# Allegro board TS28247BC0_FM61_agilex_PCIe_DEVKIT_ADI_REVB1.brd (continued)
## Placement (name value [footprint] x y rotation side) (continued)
R6090  0,DNI  [RESC1005X40L20L]  197.24 55.32 180 top
R6091  499E  [0402]  68.84 72.85 90 bottom
R6092  0  [0402]  68.89 59.01 90 bottom
R6093  0  [0402]  210.67 72.14 180 top
R6096  0  [0402]  211.18 60 0 bottom
R6097  DNI  [0402]  65.03 57.79 0 bottom
R6098  20.0K  [0402]  234.83 53.65 90 bottom
R6100  0  [RESC1005X40L20L]  199.07 55.34 180 top
R6101  0  [0402]  220.02 79.68 270 bottom
R6102  0  [0402]  228.07 55.88 45 bottom
R6103  0  [0402]  227.13 53.7 270 bottom
R6104  0  [0402]  231.58 54.33 0 bottom
R6105  0  [RESC1005X40L20L]  199.47 66.5 90 bottom
R6106  10.0K  [0402]  191.35 40.26 270 bottom
R6107  10.0K  [0402]  190.02 56.29 270 bottom
R6108  10.0K  [0402]  190.05 83.64 270 bottom
R6109  10.0K  [0402]  190.13 71.35 270 bottom
R6110  0  [RESC1005X40L20L]  190.1 72.98 90 bottom
R6111  0  [RESC1005X40L20L]  190.13 85.04 90 bottom
R6112  0  [RESC1005X40L20L]  190 57.74 90 bottom
R6113  0  [RESC1005X40L20L]  189.67 48.72 270 bottom
R6114  0  [RESC1005X40L20L]  196.1 63.93 180 bottom
R6115  0  [RESC1005X40L20L]  190.79 63.78 90 bottom
R6261  10.0K  [0402]  231.83 19.66 0 top
R6262  49.9K  [0402]  229.75 19.64 180 top
R6263  110K  [0402]  232.85 19.66 0 top
R6264  10k  [0402]  228.73 22.05 180 bottom
R6265  10.0K,DNI  [0402]  236.35 23.29 270 bottom
R6266  56.2K  [0402]  229.62 22.05 180 bottom
R6267  10.0K  [0402]  234.58 23.29 270 bottom
R6268  1.0  [0402]  235.49 24.31 90 top
R6269  10.0K,DNI  [0402]  233.84 19.64 0 top
R6270  0  [0402]  229.19 23.52 90 bottom
R6271  0  [0402]  231.78 22.48 90 bottom
R6272  10.0K,DNI  [0402]  234.78 19.64 180 top
R6273  0  [0402]  216.72 93.37 270 bottom
R6274  4.7K,DNI  [0402]  236.94 86.79 180 top
R6275  4.7K,DNI  [0402]  235.39 86.62 180 top
R6276  0.001 OHM  [RES_CSNL2512_0_005-0_006]  233.71 37.82 90 top
R6283  10.0K  [0402]  221.14 41.79 90 top
R6284  10.0K  [0402]  221.14 40.64 90 top
R6285  0  [0402]  222.03 40.64 90 bottom
R6286  0  [0402]  222.03 41.79 90 bottom
R6287  0,DNI  [0402]  221.13 37.01 90 top
R6288  0,DNI  [0402]  221.13 38.03 90 top
R6289  0  [0402]  220.58 39.27 0 top
R6290  0  [0402]  221.57 39.32 0 top
R6291  10  [0402]  230.77 37.06 270 top
R6292  10  [0402]  230.79 38.03 270 top
R6293  0  [0402]  227.74 23.02 180 bottom
R6294  0  [0402]  59.24 58.37 90 bottom
S1  PB Switch  [WURTH_6X3P5_TACT_SWITCH]  267.72 65.48 180 top
S2  PB Switch  [WURTH_6X3P5_TACT_SWITCH]  267.72 61.42 180 top
S3  PB Switch  [WURTH_6X3P5_TACT_SWITCH]  267.72 57.36 180 top
S4  PB Switch  [WURTH_6X3P5_TACT_SWITCH]  267.72 53.29 180 top
S5  PB Switch  [WURTH_6X3P5_TACT_SWITCH]  267.72 49.23 0 top
ST3  -  [SHORT]  208.62 58.88 225 bottom
ST11  -  [SHORT]  217.28 71.55 0 bottom
ST12  -  [SHORT]  68.89 60.3 0 bottom
ST13  -  [SHORT]  207.91 87.28 180 bottom
ST14  -  [SHORT]  212.48 46.18 90 bottom
ST15  -  [SHORT]  213.19 69.93 315 top
ST16  -  [SHORT]  69.02 74.09 0 bottom
ST17  -  [SHORT]  60.03 57.23 180 bottom
ST19  -  [SHORT]  231.6 47.78 180 bottom
ST20  -  [SHORT]  63.96 38.97 90 bottom
ST21  -  [SHORT]  216.01 78.56 0 top
ST31  -  [SHORT]  207.6 93.46 90 bottom
ST32  -  [SHORT]  233.76 17.94 90 top
SW1  TDA04H0SB1  [DIPSWITCH_SMT_QUAD]  213.5 31.82 180 bottom
SW2  DIPSWITCH4  [DIPSWITCH_SMT_QUAD]  8.52 71.76 90 bottom
SW3  DIPSWITCH4  [DIPSWITCH_SMT_QUAD]  8.52 64.39 90 bottom
SW4  TDA04H0SB1  [DIPSWITCH_SMT_QUAD]  8.52 46.99 90 bottom
SW5  SW_SLIDE_DPDT  [EG2207]  268.35 75.49 270 top
SW6  TDA04H0SB1  [DIPSWITCH_SMT_QUAD]  8.52 39.88 90 bottom
SW7  CVS-01TB  [DIPSWITCH_SMT_SINGLE]  265.31 42.75 0 top
TP1  TP, 0.016", Thru Hole  [30MIL_TP]  238.67 61.19 0 top
TP2  TP, 0.016", Thru Hole  [30MIL_TP]  237.37 61.22 0 top
TP16  TESTPOINT  [30MIL_TP]  214.42 27.26 0 top
TP17  TESTPOINT  [30MIL_TP]  214.42 24.72 0 top
TP19  TEST PAD  [PADSTYLE1]  211.08 99.77 0 top
TP20  TESTPOINT  [30MIL_TP]  219.37 27.26 0 top
TP28  TESTPOINT  [30MIL_TP]  203.72 53.83 0 top
TP29  TESTPOINT  [30MIL_TP]  232.39 45.16 0 top
TP30  TP, 0.016", Thru Hole  [30MIL_TP]  206.97 63.78 0 top
TP31  TP, 0.016", Thru Hole  [30MIL_TP]  205.7 63.83 0 top
TP32  TESTPOINT  [30MIL_TP]  68.1 64.67 0 top
TP33  TESTPOINT  [30MIL_TP]  65.79 79.33 0 top
TP34  TESTPOINT  [30MIL_TP]  61.73 49.58 0 top
TP35  TESTPOINT  [30MIL_TP]  61.5 63.55 0 top
TP38  TP, 0.016", Thru Hole  [30MIL_TP]  213.65 72.95 0 top
TP39  TP, 0.016", Thru Hole  [30MIL_TP]  215.15 73.23 0 top
TP41  TESTPOINT  [30MIL_TP]  215.68 63.78 0 top
TP42  TESTPOINT  [30MIL_TP]  204.68 63.66 180 bottom
TP45  TESTPOINT  [30MIL_TP]  232.37 81.69 0 top
TP46  TESTPOINT  [30MIL_TP]  230.79 61.8 0 top
TP47  TP, 0.016", Thru Hole  [30MIL_TP]  234.45 45.04 0 top
TP971  TESTPOINT  [30MIL_TP]  228.48 35.26 0 top
TP1005  -  [30MIL_TP]  236.33 22.41 0 top
U1  MAX3378E  [TSSOP-14]  103.89 98.38 90 bottom
U2  AGFB014R24_2486A  [FBGA2486A_HEX]  116.21 61.93 0 top
U3  MAX3378E  [TSSOP-14]  94.62 98.38 90 bottom
U4  MAX3378E  [TSSOP-14]  154.44 25.61 270 bottom
U5  MAX3378E  [TSSOP-14]  82.94 25.61 270 bottom
U6  MT25QU02GCBB3E12-1SIT  [T-PBGA24]  206.51 29.49 270 top
U7  KSZ9031RN  [QFN48]  28.17 86.7 270 bottom
U8  EY1501DI-ADJ  [DFN-10]  53.35 94.82 90 bottom
U9  SN74AUP1G126DCK  [SC70_TI]  25.92 67.01 90 bottom
U10  SN74AUP1T17DCKR  [SC70_TI]  16.14 73.36 0 bottom
U11  FT232R  [QFN32-FTDI]  20.71 70.82 0 bottom
U12  SN74AUP1T17DCKR  [SC70_TI]  28.96 71.96 270 bottom
U13  TPD4S012DRYR  [SON6]  17.99 104.57 180 top
U14  LSF0108PWR  [TSSOP20]  44.97 95.96 180 bottom
U15  -  [TPS22902BYFPR]  43.57 107.52 0 bottom
U16  MTFC8GAKAJCN-4M IT  [VFBGA-153]  29.47 100.15 270 bottom
U17  Si5341A-D10654-GM  [QFN64_9X9_SI5341]  48.78 25.99 0 top
U18  Si52202-A01AGM  [SI52202]  210.83 103.71 90 top
U19  510MCA50M0000AAGR  [SI510]  38.87 41.86 270 bottom
U20  FXMA2102UMX  [UMLP]  29.09 48.59 270 bottom
U21  FXMA2102UMX  [UMLP]  17.15 48.59 270 bottom
U22  FXMA2102UMX  [UMLP]  23.12 48.59 270 bottom
U23  MAX3378E  [TSSOP-14]  88.15 98.38 90 bottom
U24  MAX811  [SOT-143]  266.96 63.71 90 bottom
U25  MAX811  [SOT-143]  21.98 27.51 90 top
U26  10M04SCU169  [BGA169-0R80-11X11]  31.63 23.62 270 top
U27  TPD2EUSB30  [DRT]  5.98 26.09 90 top
U28  CY7C68013A_QFN  [QFN56]  14.36 26.57 90 top
U29  TS3A5018RSVR  [UQFN-16]  33.15 42.5 270 bottom
U30  10M16SA U169_1  [BGA169-0R80-11X11]  254.15 27.46 270 top
U32  MAX6581  [24TQFN-EP]  73.79 85.68 90 top
U33  FDMC2514SDC  [FDMC8878_VER2]  251.47 93.47 90 top
U34  FDMC2514SDC  [FDMC8878_VER2]  246.26 93.47 270 top
U35  LTC4357  [DFN6_EPAD]  256.8 101.02 0 top
U36  LTC4365-1  [DFN8-EPAD_3X2]  245.98 102.24 0 bottom
U37  LTC4359  [MSOP-8]  244.86 87.25 180 top
U38  FDMC2514SDC  [FDMC8878_VER2]  257.06 79.07 0 top
U39  FDMC2514SDC  [FDMC8878_VER2]  252.1 80.6 0 top
U40  LTC4357  [DFN6_EPAD]  261.75 79.81 270 bottom
U41  LTC4365-1  [DFN8-EPAD_3X2]  247.86 79.99 0 bottom
U42  TPS3700  [DDC]  257.69 55.45 90 top
U43  LTM4625  [LGA25]  244.61 53.29 90 top
U44  EY1501di-adj  [DFN-11]  253.25 42.5 90 top
U45  EY1501di-adj  [DFN-11]  25.49 41.08 180 bottom
U46  LTC7151SEV  [LQFN_28_5MMX4MM]  231.88 25.17 180 top
U47  LTC3888IUHG-1#PBF  [QFN40P500X800X80-53N]  199.14 61.04 0 top
U50  EY1501di-adj  [DFN-11]  210.02 51.16 270 top
U51  LTM4623EY#PBF  [BGA25C127P5X5_625X625X262]  209.28 58.22 90 top
U52  REF1112AIDBZR  [SOT23-3]  206 27.64 90 bottom
U55  LTM4678EY#PBF  [BGA144C127P12X12_1600X1600X626]  225.36 71.87 180 top
U56  LTM4608AEV#PBF  [LGA68S127P7X11_900X1500X292]  69.43 57.1 90 top
U57  LTM4643EY#PBF  [BGA77C127P7X11_900X1500X262N]  207.14 83.9 90 top
U58  LTM4643EY#PBF  [BGA77C127P7X11_900X1500X262N]  205.49 41.23 90 top
U59  TPS51200  [VSON-11]  51.57 103.96 270 bottom
U60  TPS51200  [VSON-11]  207.58 20.44 90 bottom
U61  LTM4623EY#PBF  [BGA25C127P5X5_625X625X262]  212.58 69.32 90 bottom
U62  FDMC2514  [FDMC8878_VER2]  37.73 70.82 180 bottom
U63  LTC4365-1  [DFN8-EPAD_3X2]  32.77 71.07 0 bottom
U64  EY1501di-adj  [DFN-11]  17.23 41.08 180 bottom
U65  LTM4608AEV#PBF  [LGA68S127P7X11_900X1500X292]  69.45 70.92 90 top
U66  LTM4668IY#PBF  [BGA49C80P7X7_625X625X230N]  54.53 55.87 180 bottom
U67  MAX3378E  [TSSOP-14]  73.67 98.38 90 bottom
U68  MAX3378E  [TSSOP-14]  81.29 98.38 90 bottom
U70  LTM4668IY#PBF  [BGA49C80P7X7_625X625X230N]  69.07 39.14 0 top
U71  LTM4686EV-1#PBF  [LGA108C127P9X12_1190X1600X192N]  230.26 53.04 90 top
U72  9DML0441AKILF  [24-VFQFPN]  203.84 102.06 90 bottom
U73  24AA64-I  [MSOP8]  244.99 64.21 270 top
U76  LTC7051AV#PBF  [ANALOG_LQFN-42P]  186.1 83.39 0 top
U77  LTC7051AV#PBF  [ANALOG_LQFN-42P]  186.1 70.74 0 top
U78  LTC7051AV#PBF  [ANALOG_LQFN-42P]  186.1 55.2 0 top
U79  LTC7051AV#PBF  [ANALOG_LQFN-42P]  186.1 39.02 0 top
U124  LTM4622EV#PBF  [LGA25C127P5X5_625X625X192N]  199.52 51.51 90 bottom
U125  LTM4657EY  [LTC-BGA-49-1518]  210.32 95.46 90 top
U126  INA219AIDCN  [SOT23-8P]  226.35 38.53 180 top
V1  VIA_1  [STAR_VIA]  22.74 89.74 90 bottom
Y1  25MHz  [OSC7050]  36.71 87.71 180 bottom
Y2  48MHz  [XTAL_3MMX2MM]  41.3 26.24 90 top
Y3  25.00MHz  [XTAL_FA-128]  215.53 103.2 270 top
Y4  24.00MHz  [XTAL_FA-128]  12.61 18.82 180 top

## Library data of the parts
B1 B2 = Molex_QSFPDD_Cage
C1-C3 C5 C7 C9 C11 C13 C15 C17-C19 C24-C26 C31 C34 C37-C39 C41 C45 C47 C49 C51 C53-C55 C58 C60 C63 C69 C73-C75 C77 C79 C81 C83 C85 C87 C89-C91 C96 C97 C100 C103 C106 C110 C112 C114 C116 C118 C120 C122-C124 C130 C136 C139 C142 C144 C148 C152 C157 C159 C163 C167 C173 C174 C176 C215 C237-C239 C262 C263 C266 C284-C287 C294-C324 C335-C338 C340-C344 C347-C354 C357-C367 C369-C379 C381-C391 C393 C396 C398-C404 C407-C418 C420 C426 C432 C434 C442-C444 C448 C454 C458 C459 C466 C467 C557 C561 C652 C658 C660 C661 C672 C673 C683 C687 C702-C705 C707 C708 C762-C801 C828-C834 C1232-C1235 C1244-C1246 C1249 C1250 C1292-C1297 C1427 C1440 C1441 C1446 C1447 C1450 C1472-C1502 C1518-C1524 C1654 C1655 C1816 C1822 C1823 C1840 C1868 C1873 C1874 C1895 C1900-C1902 C1904 C1914 C1933-C1935 C1940 C1956 C1957 C1966 C1967 C1975 C1976 C1978 C1979 C1990 C1994 C1996 C1998 C2002-C2004 C2007-C2010 C2012 C2017-C2020 C2025-C2028 C2031-C2033 C2038 C7777 C7778 = CAP: User Part Number: PART#; Tolerance: TOL
C4 C6 C8 C10 C12 C14 C27-C29 C35 C40 C44 C46 C48 C50 C57 C64 C70 C71 C76 C78 C80 C82 C84 C86 C98 C99 C101 C107 C109 C111 C113 C115 C117 C119 C131 C134 C140 = Cap 10000PF 50V 0402: User Part Number: PART#; Tolerance: TOL
C16 C20 C21 C32 C52 C61 C65 C66 C88 C92 C93 C104 C121 C125 C126 C137 C156 C171 C339 C427 C706 C802-C807 C1410 C1445 C1660 C1663 C1674 C1887-C1889 C1891-C1894 C1896-C1898 C1907 C1913 C1915-C1917 C1919-C1924 C1926 C1930-C1932 C1941 C1947 C1952-C1954 C1962-C1964 = CAP: Tolerance: *; User Part Number: *
C22 C23 C33 C62 C67 C68 C94 C95 C105 C127 C138 = CAP 10uF +/-10% 25V 1210: User Part Number: *; Tolerance: *
C42 = Cap 10000PF 50V 0402: User Part Number: PART#; Tolerance: TOL; signal model: CAP_0402_0.22UF_0.22uF
C43 C172 C175 C177-C214 C217 C218 C220-C222 C224-C228 C231 C232 C235 C240-C244 C247-C249 C251 C254-C256 C258-C260 C268 C269 C271-C274 C355 = CAP: User Part Number: PART#; Tolerance: TOL; signal model: CAP_0402_0.22UF_0.22uF
C128 = CAP 10uF +/-10% 25V 1210: User Part Number: *; Tolerance: *; signal model: CAP_0402_0.1UF_0.1uF
C129 C133 C325-C334 C345 = CAP: User Part Number: PART#; Tolerance: TOL; signal model: CAP_0402_0.1UF_0.1uF
C132 = Cap 10000PF 50V 0402: User Part Number: PART#; Tolerance: TOL; signal model: CAP_0402_0.1UF_0.1uF
C143 C145-C147 C149-C151 C153-C155 C158 C160-C162 C164-C166 C168-C170 C234 C236 C264 C265 C267 C356 C368 C380 C394 C397 C405 C406 C456 C457 C460-C465 C558-C560 C653-C657 C659 C662-C666 C668-C671 C682 C684-C686 C840-C842 C858-C861 C1202 C1208-C1210 C1212 C1236 C1241 C1247 C1248 C1286-C1291 C1321 C1341-C1344 C1361-C1364 C1384-C1387 C1405-C1408 C1423 C1430-C1433 C1503-C1517 C1819-C1821 C1910 C1911 C1944 C1945 C7775 C7776 = CAP: User Part Number: *; Tolerance: *
C216 C219 C223 C229 C230 C233 C250 C252 C253 C257 C261 C270 C555 C667 = CAP: User Part Number: *; Tolerance: *; signal model: CAP_0402_0.22UF_0.22uF
C245 C246 = Cap 39PF 5% 50V 0402: User Part Number: PART#; Tolerance: TOL; signal model: CAP_0402_0.22UF_0.22uF
C275 C276 = CAP: signal model: CAP_0402_0.22UF_0.22uF
C277-C283 C289-C293 C737 C836-C839 C843-C857 C1201 C1203-C1207 C1211 C1216-C1220 C1223-C1225 C1228-C1231 C1237-C1240 C1251-C1285 C1304-C1314 C1317-C1320 C1325-C1340 C1345-C1360 C1365 C1366 C1368-C1383 C1389-C1404 C1421 C1422 C1434-C1439 C1448 C1449 = CAP
C346 = CAP: User Part Number: *; Tolerance: *; signal model: CAP_0402_0.1UF_0.1uF
C395 C453 C455 C709-C711 C1665 C1818 C1839 C1909 C1943 C1995 C1997 C1999 C2034 C2036 C2039 = Cap, NP, 0402: User Part Number: PART#; Tolerance: TOL
C419 C422-C424 C445-C447 C449-C452 C1426 C1667 C1669 C1670 C1867 C1872 C1903 C1908 C1912 C1925 C1942 C1946 C1948 C1949 C1958 C1959 C1977 C1986 C1991 C2000 C2001 C2029 C2030 C2035 C2037 = Cap, NP, 1206: Tolerance: *; User Part Number: *
C421 C425 C428-C431 C433 C435-C441 C679 C1196 C1197 C1199 C1200 C1213 C1222 C1227 C1242 C1243 C1298 C1299 C1302 C1303 C1315 C1323 C1324 C1367 C1388 C1424 C1425 C1428 C1429 C1443 C1886 C1899 C1918 C1928 C1929 C7771 C7772 = PCAP
C680 = PCAP: User Part Number: *; Tolerance: *
C681 = CAP_NP: User Part Number: PART#; Tolerance: TOL
C808-C812 C814 C815 C817-C819 C821 C825 C835 C1214 C1215 = PCAP: Tolerance: TOL; User Part Number: PART#
C1525 = CAP: User Part Number: PART#; Tolerance: TOL; signal model: CAP_0402_DNI_DNI
C1550 C1656 C1673 C1817 C1833 C1834 C1848 C1849 C1859 C1860 C1875 C1876 C1950 C1960 C1987 = Cap, NP, 0402: Tolerance: TOL; User Part Number: PART#
C1659 C1951 C1961 = CAP: Tolerance: *; User Part Number: 150-3503
C1824-C1827 = T545X337K016ATE025
C1829 C1831 C1832 C1835-C1838 C1850-C1853 C1861-C1864 C1877-C1880 C1905 C1906 C1980 C1981 C1988 C1989 C1992 C1993 C2011 C7768 C7770 = Cap, NP, 1206: User Part Number: *; Tolerance: *
C1841 C1844-C1847 C1856 C1869 C1883 = CAPPOL
C1842 C1843 C1857 C1858 C1870 C1871 C1884 C1885 C2013-C2016 C2021-C2024 = Cap, NP, 0805: Tolerance: TOL; User Part Number: PART#
C1890 C7779 = TCN4227M025R0100
C7761 C7762 C7764-C7766 C7773 C7774 = CAP: Tolerance: TOL; User Part Number: PART#
C7763 = CAP NP: User Part Number: *; Tolerance: *
C7767 C7769 = Cap, NP, 1206: Tolerance: TOL; User Part Number: GRM21BR61E106K
D2 D3 D7 D9-D14 D21 D23 = LED_WURTH: User Part Number: *; Tolerance: *
D4-D6 = ESD_DIODE_DUAL
D8 = LED_0: User Part Number: *; Tolerance: *
D15 D16 = TVS_5p0SMDJ12A
D22 D24 = APHB1608CGKSYKC
D25 = PMEG2005AEL,315
FB9-FB16 FB19-FB24 FB30 FB31 FB33 FB36-FB38 FB40-FB42 FB45 L1 L2 L8 = BEAD_FERRITE_SM: User Part Number: PART#; Tolerance: TOL
FB17 FB18 FB25-FB28 = BEAD_FERRITE_SM: User Part Number: *; Tolerance: *
FB29 = INDUCTOR: User Part Number: PART#; Tolerance: TOL
HW1 = LIGHTPIPE_P-U90-1101-T00A-BP_2
J1-J4 = DDR4x72x288_1
J5 J6 = 2027180100
J7 = PCIE_Bracket_X16_1
J8 = ENET_L829-1J1T-43_2
J9 = CON2
J10 J13 = MICRO_USB_CONN
J11 = SD_SKT_1: User Part Number: *
J12 = 2-767004-2
J14 = 0702461004
J15 = FAN_Conn_0
J16 = 2X4_PCIE_ATX_1: User Part Number: PART#; Tolerance: TOL
J17 = 1x3_HDR_TH
J22 = 95278-101A04LF
L3-L7 = IND Ferrite 0603 3A/30 Ohms: User Part Number: *; Tolerance: *
L9 = IND Ferrite 0402 300mA/220: User Part Number: PART#; Tolerance: TOL
L14-L20 = INDUCTOR IRON
L23-L26 = FP1008R6-R150-R
L30 = XGL5030-351MEC
MTH1-MTH6 = MNT HOLE_1
Q1-Q4 = NMOS_3Pin: Tolerance: *; User Part Number: *
Q5-Q11 Q24-Q29 = PWRMOSFET_EN_GSD_0: Tolerance: *; User Part Number: *
Q12 = PSMN1R0-30YLD_0
Q13 = PWRMOSFET_EN_GSD_1: Tolerance: *; User Part Number: *
R1 R2 R17 R18 R54 R55 R68 R69 = RESISTOR: Tolerance: *; User Part Number: *
R3-R6 R15 R16 R21-R23 R31-R50 R53 R56 R57 R59 R66 R67 R70-R73 R80-R99 R104-R106 R108-R112 R114 R116 R120-R126 R134-R140 R143-R145 R154 R155 R157-R163 R165-R167 R171-R180 R187 R188 R190 R196 R201-R204 R206 R208-R214 R216 R236 R241-R245 R247 R260 R261 R263 R265-R305 R307 R308 R310 R312 R313 R315 R318-R320 R322-R326 R328-R332 R334-R340 R344-R346 R348-R351 R354 R356 R357 R361 R363-R365 R367 R368 R370 R371 R373 R374 R377-R380 R382 R385 R387 R390 R395-R402 R405-R407 R409-R412 R414-R419 R421 R423-R431 R433-R449 R546-R549 R647-R658 R668 R669 R671-R677 R680-R682 R703-R711 R714-R724 R729-R735 R773-R788 R793 R794 R801-R823 R828-R830 R832 R833 R978 R5757 R5758 R5772-R5774 R5780 R5788 R5789 R5928 R5930 R5932 R5934 R5939-R5942 R5957 R5960 R5963-R5978 R5981-R5983 R5985 R5988-R5992 R5994 R5995 R5997-R6001 R6004 R6006 R6011 R6012 R6015-R6024 R6026-R6037 R6039-R6043 R6045 R6056 R6059-R6062 R6075-R6077 R6083-R6086 R6091-R6093 R6096-R6098 R6101-R6104 R6106-R6109 R6273-R6275 R6283-R6294 = RESISTOR: User Part Number: PART#; Tolerance: TOL
R7-R9 R24 R25 R58 R60 R74 R246 R248-R259 R262 R264 R408 R420 R470 R471 R514-R516 R678 R679 = RES 0 OHM 5% 1/16W 0402 SMD: User Part Number: PART#; Tolerance: TOL; signal model: RES_0_OHM_5%_1/16W_0402_SMD_0402_0_0
R10 R26 R61 R75 R107 R117 R118 R789-R792 = RESISTOR: User Part Number: PART#; Tolerance: TOL; signal model: RESISTOR_0402_10.0K_10.0K
R11-R13 R27-R29 R62-R64 R76-R78 R142 R147 R149 R150 R153 R358 R831 = RESISTOR: User Part Number: PART#; Tolerance: TOL; signal model: RESISTOR_0402_DNI_DNI
R14 R19 R20 R30 R65 R79 R189 R191-R195 R205 R207 = RESISTOR: User Part Number: *; Tolerance: *
R100 R101 R238 R239 R321 R327 R670 R797-R800 R824-R827 R834 R5980 R6002 R6003 R6005 R6007 R6014 = RES 0 OHM 5% 1/16W 0402 SMD: User Part Number: PART#; Tolerance: TOL
R102 R103 R141 R146 R148 R151 R152 R156 = RESISTOR: User Part Number: PART#; Tolerance: TOL; signal model: RESISTOR_0402_4.7K_4.7K
R113 = RESISTOR_0402: User Part Number: PART#; Tolerance: TOL; signal model: RESISTOR_0402_0402_33_33
R115 R119 R341-R343 R347 R352 R353 R355 R359 = RESISTOR: User Part Number: PART#; Tolerance: TOL; signal model: RESISTOR_0402_1K_1K
R127 R129-R133 R169 R218-R226 = RESISTOR: User Part Number: PART#; Tolerance: TOL; signal model: RESISTOR_0402_0402_33_33
R128 R197-R200 R391-R394 = RESISTOR: User Part Number: PART#; Tolerance: TOL; signal model: RESISTOR_0402_0_0
R164 R333 = R: User Part Number: PART#; Tolerance: TOL
R181-R186 R215 R217 = RESISTOR: User Part Number: PART#; Tolerance: TOL; signal model: RESISTOR_0402_1.00K_1.00K
R227-R235 = RESISTOR: User Part Number: PART#; Tolerance: TOL; signal model: RESISTOR_0402_10K_10K
R306 R309 R311 R314 R316 R317 = RESISTOR_0: User Part Number: PART#; Tolerance: TOL
R360 R362 R369 R372 R375 R376 R381 R383 R384 R386 = RES 10 OHM 1.0% 1/16W 0402: User Part Number: PART#; Tolerance: TOL
R404 R413 R422 R432 R5993 R5996 R6063 R6067 R6074 = RES: User Part Number: PART#; Tolerance: TOL
R667 = RESISTOR_0603: Tolerance: *; User Part Number: *
R873-R877 R6264 = Resistor, 0402: Tolerance: TOL; User Part Number: PART#
R5776 R5777 R5785 R5787 R5929 R5931 R5933 R5935-R5938 R5958 R5984 R5986 R5987 R6013 R6038 R6044 R6055 R6057 R6058 R6065 R6066 R6071-R6073 R6078 R6079 = Resistor, 0402: User Part Number: PART#; Tolerance: TOL
R5784 R5786 = RESISTOR_0402: User Part Number: PART#; Tolerance: TOL
R5943-R5947 R5949 R5951 R5952 R5954 R5955 R5961 R5962 R6087-R6090 R6100 R6105 R6110-R6115 = Resistor, 0402_0: Tolerance: TOL; User Part Number: PART#
R5948 = Resistor, 0603_0: Tolerance: *; User Part Number: *
R5956 = res: User Part Number: PART#; Tolerance: TOL; alternate symbols: ((T:0402_BGA;B:0402_BGA))
R6008 R6276 = CSNL2512FT5L00
R6261-R6263 R6265-R6272 = RESISTOR: Tolerance: TOL; User Part Number: PART#
S1-S5 = TS-A02SA-2-S100_0: User Part Number: *
ST3 ST11-ST17 ST19-ST21 ST31 ST32 = SHORT: User Part Number: *
SW1-SW4 SW6 = SPST4
SW5 = SW_SLIDE_DPDT: User Part Number: PART#; Tolerance: TOL
SW7 = SPST4_0
TP1 TP2 TP16 TP17 TP20 TP28 TP30 TP31 TP38 TP39 TP47 TP971 TP1005 = TP, 0.016", Thru Hole
TP19 = PAD_STYLE_C
TP29 TP32-TP35 TP41 TP42 TP45 TP46 = TESTPOINT
U1 U3-U5 U23 U67 U68 = MAX3378E_0: User Part Number: PN; Tolerance: TOL
U2 = FM6_2486A_V1.5
U6 = MT25QU01GBBB: User Part Number: *; Tolerance: *
U7 = KSZ9031RN_4
U8 = EY1501DI-ADJ
U9 = SN74AUP1G126DCK
U10 U12 = SN74AUP1G17DCK
U11 = FT232R_2: User Part Number: *
U13 = TPD4S012DRYR
U14 = LSF0108PWR
U15 = TPS22902BYFPR
U16 = MTFC8GAKAJCN-4M IT
U17 = Si5341A-A-GM_1
U18 = Si52202-A01AGM
U19 = Si510-DualCMOS
U20-U22 = FXMA2102UMX
U24 U25 = MAX811: Tolerance: TOL; User Part Number: PART#
U26 = 10M04SCU169
U27 = TPD2EUSB30: Tolerance: *; User Part Number: *
U28 = CY7C68013A_56QFN: User Part Number: *
U29 = TS3A5018RSVR_0
U30 = 10M16SA U169_1
U32 = MAX6581_0
U33 U34 U38 U39 U62 = FDMC8878_VER2: User Part Number: *
U35 U40 = LTC4357: User Part Number: *
U36 U41 U63 = LTC4365_DFN: User Part Number: *
U37 = LTC4359
U42 = TPS3700: User Part Number: pn
U43 = LTC4625EY
U44 U45 U50 U64 = EY1501di-adj
U46 = LTC3543EDCB_0
U47 = LTC3888IUHG-1#PBF
U51 U61 = LTM4623EY#PBF
U52 = REF1112
U55 = LTM4678EY#PBF
U56 U65 = LTM4608AEV#PBF_V1
U57 U58 = LTM4643EY#PBF
U59 U60 = TPS51200: User Part Number: *
U66 U70 = LTM4668IY#PBF
U71 = LTM4686EV-1#PBF
U72 = 9DML0451AKILF
U73 = 24AA64-I
U76-U79 = LTC7051AV#PBF
U124 = LTM4622EV#PBF
U125 = LTM4657-BGA_0
U126 = INA219AIDCN
V1 = VIA_1
Y1 = OSC_ALT
Y2 = CRYSTAL_SM_13
Y3 Y4 = CRYSTAL_SM_13: User Part Number: *

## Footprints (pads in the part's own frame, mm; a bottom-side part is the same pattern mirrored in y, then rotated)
1X3_HDR_TH
  rect 1.524x1.524 hole 1.016: 1(0,0)
  round 1.524 hole 1.016: 2(2.54,0) 3(5.08,0)
8MM_CAN
  rect 2.032x4.013 smd: 1(0,3.257) 2(0,-3.257)
24-VFQFPN
  oval 0.787x0.279 smd: 1(-1.994,1.25) 2(-1.994,0.75) 3(-1.994,0.25) 4(-1.994,-0.25) 5(-1.994,-0.75) 6(-1.994,-1.25) 13(1.994,-1.25) 14(1.994,-0.75) 15(1.994,-0.25) 16(1.994,0.25) 17(1.994,0.75) 18(1.994,1.25)
  oval 0.279x0.787 smd: 7(-1.25,-1.994) 8(-0.75,-1.994) 9(-0.25,-1.994) 10(0.25,-1.994) 11(0.75,-1.994) 12(1.25,-1.994) 19(1.25,1.994) 20(0.75,1.994) 21(0.25,1.994) 22(-0.25,1.994) 23(-0.75,1.994) 24(-1.25,1.994)
  rect 2.413x2.413 smd: 25(0,0)
24TQFN-EP
  oval 0.787x0.279 smd: 1(-1.994,1.25) 2(-1.994,0.75) 3(-1.994,0.25) 4(-1.994,-0.25) 5(-1.994,-0.75) 6(-1.994,-1.25) 13(1.994,-1.25) 14(1.994,-0.75) 15(1.994,-0.25) 16(1.994,0.25) 17(1.994,0.75) 18(1.994,1.25)
  oval 0.279x0.787 smd: 7(-1.25,-1.994) 8(-0.75,-1.994) 9(-0.25,-1.994) 10(0.25,-1.994) 11(0.75,-1.994) 12(1.25,-1.994) 19(1.25,1.994) 20(0.75,1.994) 21(0.25,1.994) 22(-0.25,1.994) 23(-0.75,1.994) 24(-1.25,1.994)
  rect 2.413x2.413 smd: 25(0,0)
30MIL_TP
  round 0.762 smd: 1(0,0)
0201
  rect 0.45x0.4 smd: 1(-0.35,0) 2(0.35,0)
0402
  rect 0.508x0.508 smd: 1(0,0.445) 2(0,-0.445)
0603
  rect 1.016x1.016 smd: 1(-0.762,0) 2(0.762,0)
0805
  rect 1.6x1.321 smd: 1(0,0.95) 2(0,-0.95)
1206
  rect 1.27x1.778 smd: 1(-1.524,0) 2(1.524,0)
1210
  rect 1.27x2.794 smd: 1(-1.524,0) 2(1.524,0)
1411
  rect 1.524x2.464 smd: 1(-1.612,0) 2(1.612,0)
2917
  rect 2.54x2.743 smd: 1(-3.175,0) 2(3.175,0)
7343P
  rect 2.54x2.743 smd: 1(-3.175,0) 2(3.175,0)
2027180100
  oval 1.6x0.356 smd: 1(2.4,7) 2(2.4,6.2) 3(2.4,5.4) 4(2.4,4.6) 5(2.4,3.8) 6(2.4,3) 7(2.4,2.2) 8(2.4,1.4) 9(2.4,0.6) 10(2.4,-0.2) 11(2.4,-1) 12(2.4,-1.8) 13(2.4,-2.6) 14(2.4,-3.4) 15(2.4,-4.2) 16(2.4,-5) 17(2.4,-5.8) 18(2.4,-6.6) 19(2.4,-7.4) 20(11.19,-7) 21(11.19,-6.2) 22(11.19,-5.4) 23(11.19,-4.6) 24(11.19,-3.8) 25(11.19,-3) 26(11.19,-2.2) 27(11.19,-1.4) 28(11.19,-0.6) 29(11.19,0.2) 30(11.19,1) 31(11.19,1.8) 32(11.19,2.6) 33(11.19,3.4) 34(11.19,4.2) 35(11.19,5) 36(11.19,5.8) 37(11.19,6.6) 38(11.19,7.4) 39(5.33,7) 40(5.33,6.2) 41(5.33,5.4) 42(5.33,4.6) 43(5.33,3.8) 44(5.33,3) 45(5.33,2.2) 46(5.33,1.4) 47(5.33,0.6) 48(5.33,-0.2) 49(5.33,-1) 50(5.33,-1.8) 51(5.33,-2.6) 52(5.33,-3.4) 53(5.33,-4.2) 54(5.33,-5) 55(5.33,-5.8) 56(5.33,-6.6) 57(5.33,-7.4) 58(8.26,-7) 59(8.26,-6.2) 60(8.26,-5.4) 61(8.26,-4.6) 62(8.26,-3.8) 63(8.26,-3) 64(8.26,-2.2) 65(8.26,-1.4) 66(8.26,-0.6) 67(8.26,0.2) 68(8.26,1) 69(8.26,1.8) 70(8.26,2.6) 71(8.26,3.4) 72(8.26,4.2) 73(8.26,5) 74(8.26,5.8) 75(8.26,6.6) 76(8.26,7.4)
  round 3.023 hole 1.549: 77(-9.1,8.4) 78(-9.1,-8.4)
AMPHENOL_95278-X01X04LF
  rect 1.27x2.54 smd: 1(-1.27,-2.73) 2(-1.27,2.73) 3(1.27,-2.73) 4(1.27,2.73)
ANALOG_LQFN-42P
  rect 0.7x0.25 smd: 1(-2.4,3.5) 2(-2.4,3) 3(-2.4,2.5) 4(-2.4,2) 5(-2.4,1.5) 6(-2.4,1) 7(-2.4,0.5) 9(-2.4,-0.5) 10(-2.4,-1) 11(-2.4,-1.5) 12(-2.4,-2) 13(-2.4,-2.5) 14(-2.4,-3) 15(-2.4,-3.5) 22(2.4,-3.5) 23(2.4,-3) 24(2.4,-2.5) 25(2.4,-2) 26(2.4,-1.5) 27(2.4,-1) 28(2.4,-0.5) 29(2.4,0) 30(2.4,0.5) 31(2.4,1) 32(2.4,1.5) 33(2.4,2) 34(2.4,2.5) 35(2.4,3) 36(2.4,3.5)
  custom 0.312x0.312 smd: 8(-2.4,0)
  custom 0.238x0.238 smd: 16(-2,-3.9) 42(-2,3.9)
  rect 0.25x0.7 smd: 17(-1,-3.9) 19(0,-3.9) 20(1,-3.9) 38(1,3.9) 39(0,3.9) 41(-1,3.9)
  custom 0.35x0.35 smd: 18(-0.5,-3.9) 40(-0.5,3.9)
  custom 0.288x0.288 smd: 21(1.5,-3.9) 37(1.5,3.9)
  rect 0.7x1.5 smd: 43(0.85,0)
B2
  rect 1.778x2.54 smd: 1(-1.524,0) 2(1.524,0)
BEL_L829-1J1T-43
  round 3.251 hole 3.251 unplated: (-9.906,-6.604) (-0.254,-6.604)
  rect 1.397x1.397 hole 0.889: 1(0,0)
  round 1.397 hole 0.889: 2(-2.032,0) 3(-4.064,0) 4(-6.096,0) 5(-8.128,0) 6(-10.16,0) 7(1.016,2.54) 8(-1.016,2.54) 9(-3.048,2.54) 10(-7.112,2.54) 11(-9.144,2.54) 12(-11.176,2.54)
  round 1.778 hole 1.27: 13(2.438,-12.954) 14(2.438,-15.494) 15(-12.598,-10.414) 16(-12.598,-12.954) 17(-12.598,-15.494)
  round 2.337 hole 1.575: 18(3.708,-6.604) 19(-13.868,-6.604)
BGA25C127P5X5_625X625X262
  round 0.63 smd: A1(-2.54,2.54) A2(-1.27,2.54) A3(0,2.54) A4(1.27,2.54) A5(2.54,2.54) B1(-2.54,1.27) B2(-1.27,1.27) B3(0,1.27) B4(1.27,1.27) B5(2.54,1.27) C1(-2.54,0) C2(-1.27,0) C3(0,0) C4(1.27,0) C5(2.54,0) D1(-2.54,-1.27) D2(-1.27,-1.27) D3(0,-1.27) D4(1.27,-1.27) D5(2.54,-1.27) E1(-2.54,-2.54) E2(-1.27,-2.54) E3(0,-2.54) E4(1.27,-2.54) E5(2.54,-2.54)
BGA49C80P7X7_625X625X230N
  round 0.45 smd: A1(-2.4,2.4) A2(-1.6,2.4) A3(-0.8,2.4) A4(0,2.4) A5(0.8,2.4) A6(1.6,2.4) A7(2.4,2.4) B1(-2.4,1.6) B2(-1.6,1.6) B3(-0.8,1.6) B4(0,1.6) B5(0.8,1.6) B6(1.6,1.6) B7(2.4,1.6) C1(-2.4,0.8) C2(-1.6,0.8) C3(-0.8,0.8) C4(0,0.8) C5(0.8,0.8) C6(1.6,0.8) C7(2.4,0.8) D1(-2.4,0) D2(-1.6,0) D3(-0.8,0) D4(0,0) D5(0.8,0) D6(1.6,0) D7(2.4,0) E1(-2.4,-0.8) E2(-1.6,-0.8) E3(-0.8,-0.8) E4(0,-0.8) E5(0.8,-0.8) E6(1.6,-0.8) E7(2.4,-0.8) F1(-2.4,-1.6) F2(-1.6,-1.6) F3(-0.8,-1.6) F4(0,-1.6) F5(0.8,-1.6) F6(1.6,-1.6) F7(2.4,-1.6) G1(-2.4,-2.4) G2(-1.6,-2.4) G3(-0.8,-2.4) G4(0,-2.4) G5(0.8,-2.4) G6(1.6,-2.4) G7(2.4,-2.4)
BGA77C127P7X11_900X1500X262N
  round 0.61 smd: A1(-3.81,6.35) A2(-2.54,6.35) A3(-1.27,6.35) A4(0,6.35) A5(1.27,6.35) A6(2.54,6.35) A7(3.81,6.35) B1(-3.81,5.08) B2(-2.54,5.08) B3(-1.27,5.08) B4(0,5.08) B5(1.27,5.08) B6(2.54,5.08) B7(3.81,5.08) C1(-3.81,3.81) C2(-2.54,3.81) C3(-1.27,3.81) C4(0,3.81) C5(1.27,3.81) C6(2.54,3.81) C7(3.81,3.81) D1(-3.81,2.54) D2(-2.54,2.54) D3(-1.27,2.54) D4(0,2.54) D5(1.27,2.54) D6(2.54,2.54) D7(3.81,2.54) E1(-3.81,1.27) E2(-2.54,1.27) E3(-1.27,1.27) E4(0,1.27) E5(1.27,1.27) E6(2.54,1.27) E7(3.81,1.27) F1(-3.81,0) F2(-2.54,0) F3(-1.27,0) F4(0,0) F5(1.27,0) F6(2.54,0) F7(3.81,0) G1(-3.81,-1.27) G2(-2.54,-1.27) G3(-1.27,-1.27) G4(0,-1.27) G5(1.27,-1.27) G6(2.54,-1.27) G7(3.81,-1.27) H1(-3.81,-2.54) H2(-2.54,-2.54) H3(-1.27,-2.54) H4(0,-2.54) H5(1.27,-2.54) H6(2.54,-2.54) H7(3.81,-2.54) J1(-3.81,-3.81) J2(-2.54,-3.81) J3(-1.27,-3.81) J4(0,-3.81) J5(1.27,-3.81) J6(2.54,-3.81) J7(3.81,-3.81) K1(-3.81,-5.08) K2(-2.54,-5.08) K3(-1.27,-5.08) K4(0,-5.08) K5(1.27,-5.08) K6(2.54,-5.08) K7(3.81,-5.08) L1(-3.81,-6.35) L2(-2.54,-6.35) L3(-1.27,-6.35) L4(0,-6.35) L5(1.27,-6.35) L6(2.54,-6.35) L7(3.81,-6.35)
BGA144C127P12X12_1600X1600X626
  round 0.61 smd: A1(-6.985,6.985) A2(-5.715,6.985) A3(-4.445,6.985) A4(-3.175,6.985) A5(-1.905,6.985) A6(-0.635,6.985) A7(0.635,6.985) A8(1.905,6.985) A9(3.175,6.985) A10(4.445,6.985) A11(5.715,6.985) A12(6.985,6.985) B1(-6.985,5.715) B2(-5.715,5.715) B3(-4.445,5.715) B4(-3.175,5.715) B5(-1.905,5.715) B6(-0.635,5.715) B7(0.635,5.715) B8(1.905,5.715) B9(3.175,5.715) B10(4.445,5.715) B11(5.715,5.715) B12(6.985,5.715) C1(-6.985,4.445) C2(-5.715,4.445) C3(-4.445,4.445) C4(-3.175,4.445) C5(-1.905,4.445) C6(-0.635,4.445) C7(0.635,4.445) C8(1.905,4.445) C9(3.175,4.445) C10(4.445,4.445) C11(5.715,4.445) C12(6.985,4.445) D1(-6.985,3.175) D2(-5.715,3.175) D3(-4.445,3.175) D4(-3.175,3.175) D5(-1.905,3.175) D6(-0.635,3.175) D7(0.635,3.175) D8(1.905,3.175) D9(3.175,3.175) D10(4.445,3.175) D11(5.715,3.175) D12(6.985,3.175) E1(-6.985,1.905) E2(-5.715,1.905) E3(-4.445,1.905) E4(-3.175,1.905) E5(-1.905,1.905) E6(-0.635,1.905) E7(0.635,1.905) E8(1.905,1.905) E9(3.175,1.905) E10(4.445,1.905) E11(5.715,1.905) E12(6.985,1.905) F1(-6.985,0.635) F2(-5.715,0.635) F3(-4.445,0.635) F4(-3.175,0.635) F5(-1.905,0.635) F6(-0.635,0.635) F7(0.635,0.635) F8(1.905,0.635) F9(3.175,0.635) F10(4.445,0.635) F11(5.715,0.635) F12(6.985,0.635) G1(-6.985,-0.635) G2(-5.715,-0.635) G3(-4.445,-0.635) G4(-3.175,-0.635) G5(-1.905,-0.635) G6(-0.635,-0.635) G7(0.635,-0.635) G8(1.905,-0.635) G9(3.175,-0.635) G10(4.445,-0.635) G11(5.715,-0.635) G12(6.985,-0.635) H1(-6.985,-1.905) H2(-5.715,-1.905) H3(-4.445,-1.905) H4(-3.175,-1.905) H5(-1.905,-1.905) H6(-0.635,-1.905) H7(0.635,-1.905) H8(1.905,-1.905) H9(3.175,-1.905) H10(4.445,-1.905) H11(5.715,-1.905) H12(6.985,-1.905) J1(-6.985,-3.175) J2(-5.715,-3.175) J3(-4.445,-3.175) J4(-3.175,-3.175) J5(-1.905,-3.175) J6(-0.635,-3.175) J7(0.635,-3.175) J8(1.905,-3.175) J9(3.175,-3.175) J10(4.445,-3.175) J11(5.715,-3.175) J12(6.985,-3.175) K1(-6.985,-4.445) K2(-5.715,-4.445) K3(-4.445,-4.445) K4(-3.175,-4.445) K5(-1.905,-4.445) K6(-0.635,-4.445) K7(0.635,-4.445) K8(1.905,-4.445) K9(3.175,-4.445) K10(4.445,-4.445) K11(5.715,-4.445) K12(6.985,-4.445) L1(-6.985,-5.715) L2(-5.715,-5.715) L3(-4.445,-5.715) L4(-3.175,-5.715) L5(-1.905,-5.715) L6(-0.635,-5.715) L7(0.635,-5.715) L8(1.905,-5.715) L9(3.175,-5.715) L10(4.445,-5.715) L11(5.715,-5.715) L12(6.985,-5.715) M1(-6.985,-6.985) M2(-5.715,-6.985) M3(-4.445,-6.985) M4(-3.175,-6.985) M5(-1.905,-6.985) M6(-0.635,-6.985) M7(0.635,-6.985) M8(1.905,-6.985) M9(3.175,-6.985) M10(4.445,-6.985) M11(5.715,-6.985) M12(6.985,-6.985)
BGA169-0R80-11X11
  round 0.406 smd: A1(-4.8,4.8) A2(-4,4.8) A3(-3.2,4.8) A4(-2.4,4.8) A5(-1.6,4.8) A6(-0.8,4.8) A7(0,4.8) A8(0.8,4.8) A9(1.6,4.8) A10(2.4,4.8) A11(3.2,4.8) A12(4,4.8) A13(4.8,4.8) B1(-4.8,4) B2(-4,4) B3(-3.2,4) B4(-2.4,4) B5(-1.6,4) B6(-0.8,4) B7(0,4) B8(0.8,4) B9(1.6,4) B10(2.4,4) B11(3.2,4) B12(4,4) B13(4.8,4) C1(-4.8,3.2) C2(-4,3.2) C3(-3.2,3.2) C4(-2.4,3.2) C5(-1.6,3.2) C6(-0.8,3.2) C7(0,3.2) C8(0.8,3.2) C9(1.6,3.2) C10(2.4,3.2) C11(3.2,3.2) C12(4,3.2) C13(4.8,3.2) D1(-4.8,2.4) D2(-4,2.4) D3(-3.2,2.4) D4(-2.4,2.4) D5(-1.6,2.4) D6(-0.8,2.4) D7(0,2.4) D8(0.8,2.4) D9(1.6,2.4) D10(2.4,2.4) D11(3.2,2.4) D12(4,2.4) D13(4.8,2.4) E1(-4.8,1.6) E2(-4,1.6) E3(-3.2,1.6) E4(-2.4,1.6) E5(-1.6,1.6) E6(-0.8,1.6) E7(0,1.6) E8(0.8,1.6) E9(1.6,1.6) E10(2.4,1.6) E11(3.2,1.6) E12(4,1.6) E13(4.8,1.6) F1(-4.8,0.8) F2(-4,0.8) F3(-3.2,0.8) F4(-2.4,0.8) F5(-1.6,0.8) F6(-0.8,0.8) F7(0,0.8) F8(0.8,0.8) F9(1.6,0.8) F10(2.4,0.8) F11(3.2,0.8) F12(4,0.8) F13(4.8,0.8) G1(-4.8,0) G2(-4,0) G3(-3.2,0) G4(-2.4,0) G5(-1.6,0) G6(-0.8,0) G7(0,0) G8(0.8,0) G9(1.6,0) G10(2.4,0) G11(3.2,0) G12(4,0) G13(4.8,0) H1(-4.8,-0.8) H2(-4,-0.8) H3(-3.2,-0.8) H4(-2.4,-0.8) H5(-1.6,-0.8) H6(-0.8,-0.8) H7(0,-0.8) H8(0.8,-0.8) H9(1.6,-0.8) H10(2.4,-0.8) H11(3.2,-0.8) H12(4,-0.8) H13(4.8,-0.8) J1(-4.8,-1.6) J2(-4,-1.6) J3(-3.2,-1.6) J4(-2.4,-1.6) J5(-1.6,-1.6) J6(-0.8,-1.6) J7(0,-1.6) J8(0.8,-1.6) J9(1.6,-1.6) J10(2.4,-1.6) J11(3.2,-1.6) J12(4,-1.6) J13(4.8,-1.6) K1(-4.8,-2.4) K2(-4,-2.4) K3(-3.2,-2.4) K4(-2.4,-2.4) K5(-1.6,-2.4) K6(-0.8,-2.4) K7(0,-2.4) K8(0.8,-2.4) K9(1.6,-2.4) K10(2.4,-2.4) K11(3.2,-2.4) K12(4,-2.4) K13(4.8,-2.4) L1(-4.8,-3.2) L2(-4,-3.2) L3(-3.2,-3.2) L4(-2.4,-3.2) L5(-1.6,-3.2) L6(-0.8,-3.2) L7(0,-3.2) L8(0.8,-3.2) L9(1.6,-3.2) L10(2.4,-3.2) L11(3.2,-3.2) L12(4,-3.2) L13(4.8,-3.2) M1(-4.8,-4) M2(-4,-4) M3(-3.2,-4) M4(-2.4,-4) M5(-1.6,-4) M6(-0.8,-4) M7(0,-4) M8(0.8,-4) M9(1.6,-4) M10(2.4,-4) M11(3.2,-4) M12(4,-4) M13(4.8,-4) N1(-4.8,-4.8) N2(-4,-4.8) N3(-3.2,-4.8) N4(-2.4,-4.8) N5(-1.6,-4.8) N6(-0.8,-4.8) N7(0,-4.8) N8(0.8,-4.8) N9(1.6,-4.8) N10(2.4,-4.8) N11(3.2,-4.8) N12(4,-4.8) N13(4.8,-4.8)
C0402
  rect 0.508x0.508 smd: 1(0,0.445) 2(0,-0.445)
C1206
  rect 1.27x1.778 smd: 1(-1.524,0) 2(1.524,0)
CAPC1005X60L20L
  rect 0.508x0.508 smd: 1(0,0.445) 2(0,-0.445)
CAPC2012X110L50L
  rect 1.6x1.321 smd: 1(0,0.95) 2(0,-0.95)
CAPC3216X135L50N
  rect 1.27x1.778 smd: 1(-1.524,0) 2(1.524,0)
CAPMP7343X300L130X240N_P079IN
  rect 2.54x2.743 smd: 1(-3.175,0) 2(3.175,0)
CC0603N
  rect 1.016x1.016 smd: 1(-0.762,0) 2(0.762,0)
CT7343-43_CUS
  rect 2.232x2.8 smd: 1(-2.85,0) 2(2.85,0)
CT7361-20
  rect 2.74x4.88 smd: 1(-2.84,0)
  rect 3.94x4.88 smd: 2(2.24,0)
D2E
  rect 2.591x2.667 smd: 1(-3.2,0) 2(3.2,0)
DDC
  rect 0.6x1.1 smd: 1(-0.95,-1.25) 2(0,-1.25) 3(0.95,-1.25) 4(0.95,1.25) 5(0,1.25) 6(-0.95,1.25)
DDR4DIMM_SMT
  round 3.226 hole 2.464: (-68.975,0) (68.975,0)
  oval 1.727x2.972 hole 1.219x2.464: (5.575,0)
  rect 0.584x1.803 smd: 1(-63.325,-2.3) 2(-62.475,-2.3) 3(-61.625,-2.3) 4(-60.775,-2.3) 5(-59.925,-2.3) 6(-59.075,-2.3) 7(-58.225,-2.3) 8(-57.375,-2.3) 9(-56.525,-2.3) 10(-55.675,-2.3) 11(-54.825,-2.3) 12(-53.975,-2.3) 13(-53.125,-2.3) 14(-52.275,-2.3) 15(-51.425,-2.3) 16(-50.575,-2.3) 17(-49.725,-2.3) 18(-48.875,-2.3) 19(-48.025,-2.3) 20(-47.175,-2.3) 21(-46.325,-2.3) 22(-45.475,-2.3) 23(-44.625,-2.3) 24(-43.775,-2.3) 25(-42.925,-2.3) 26(-42.075,-2.3) 27(-41.225,-2.3) 28(-40.375,-2.3) 29(-39.525,-2.3) 30(-38.675,-2.3) 31(-37.825,-2.3) 32(-36.975,-2.3) 33(-36.125,-2.3) 34(-35.275,-2.3) 35(-34.425,-2.3) 36(-33.575,-2.3) 37(-32.725,-2.3) 38(-31.875,-2.3) 39(-31.025,-2.3) 40(-30.175,-2.3) 41(-29.325,-2.3) 42(-28.475,-2.3) 43(-27.625,-2.3) 44(-26.775,-2.3) 45(-25.925,-2.3) 46(-25.075,-2.3) 47(-24.225,-2.3) 48(-23.375,-2.3) 49(-22.525,-2.3) 50(-21.675,-2.3) 51(-20.825,-2.3) 52(-19.975,-2.3) 53(-19.125,-2.3) 54(-18.275,-2.3) 55(-17.425,-2.3) 56(-16.575,-2.3) 57(-15.725,-2.3) 58(-14.875,-2.3) 59(-14.025,-2.3) 60(-13.175,-2.3) 61(-12.325,-2.3) 62(-11.475,-2.3) 63(-10.625,-2.3) 64(-9.775,-2.3) 65(-8.925,-2.3) 66(-8.075,-2.3) 67(-7.225,-2.3) 68(-6.375,-2.3) 69(-5.525,-2.3) 70(-4.675,-2.3) 71(-3.825,-2.3) 72(-2.975,-2.3) 73(-2.125,-2.3) 74(-1.275,-2.3) 75(-0.425,-2.3) 76(0.425,-2.3) 77(1.275,-2.3) 78(7.225,-2.3) 79(8.075,-2.3) 80(8.925,-2.3) 81(9.775,-2.3) 82(10.625,-2.3) 83(11.475,-2.3) 84(12.325,-2.3) 85(13.175,-2.3) 86(14.025,-2.3) 87(14.875,-2.3) 88(15.725,-2.3) 89(16.575,-2.3) 90(17.425,-2.3) 91(18.275,-2.3) 92(19.125,-2.3) 93(19.975,-2.3) 94(20.825,-2.3) 95(21.675,-2.3) 96(22.525,-2.3) 97(23.375,-2.3) 98(24.225,-2.3) 99(25.075,-2.3) 100(25.925,-2.3) 101(26.775,-2.3) 102(27.625,-2.3) 103(28.475,-2.3) 104(29.325,-2.3) 105(30.175,-2.3) 106(31.025,-2.3) 107(31.875,-2.3) 108(32.725,-2.3) 109(33.575,-2.3) 110(34.425,-2.3) 111(35.275,-2.3) 112(36.125,-2.3) 113(36.975,-2.3) 114(37.825,-2.3) 115(38.675,-2.3) 116(39.525,-2.3) 117(40.375,-2.3) 118(41.225,-2.3) 119(42.075,-2.3) 120(42.925,-2.3) 121(43.775,-2.3) 122(44.625,-2.3) 123(45.475,-2.3) 124(46.325,-2.3) 125(47.175,-2.3) 126(48.025,-2.3) 127(48.875,-2.3) 128(49.725,-2.3) 129(50.575,-2.3) 130(51.425,-2.3) 131(52.275,-2.3) 132(53.125,-2.3) 133(53.975,-2.3) 134(54.825,-2.3) 135(55.675,-2.3) 136(56.525,-2.3) 137(57.375,-2.3) 138(58.225,-2.3) 139(59.075,-2.3) 140(59.925,-2.3) 141(60.775,-2.3) 142(61.625,-2.3) 143(62.475,-2.3) 144(63.325,-2.3) 145(-63.325,2.3) 146(-62.475,2.3) 147(-61.625,2.3) 148(-60.775,2.3) 149(-59.925,2.3) 150(-59.075,2.3) 151(-58.225,2.3) 152(-57.375,2.3) 153(-56.525,2.3) 154(-55.675,2.3) 155(-54.825,2.3) 156(-53.975,2.3) 157(-53.125,2.3) 158(-52.275,2.3) 159(-51.425,2.3) 160(-50.575,2.3) 161(-49.725,2.3) 162(-48.875,2.3) 163(-48.025,2.3) 164(-47.175,2.3) 165(-46.325,2.3) 166(-45.475,2.3) 167(-44.625,2.3) 168(-43.775,2.3) 169(-42.925,2.3) 170(-42.075,2.3) 171(-41.225,2.3) 172(-40.375,2.3) 173(-39.525,2.3) 174(-38.675,2.3) 175(-37.825,2.3) 176(-36.975,2.3) 177(-36.125,2.3) 178(-35.275,2.3) 179(-34.425,2.3) 180(-33.575,2.3) 181(-32.725,2.3) 182(-31.875,2.3) 183(-31.025,2.3) 184(-30.175,2.3) 185(-29.325,2.3) 186(-28.475,2.3) 187(-27.625,2.3) 188(-26.775,2.3) 189(-25.925,2.3) 190(-25.075,2.3) 191(-24.225,2.3) 192(-23.375,2.3) 193(-22.525,2.3) 194(-21.675,2.3) 195(-20.825,2.3) 196(-19.975,2.3) 197(-19.125,2.3) 198(-18.275,2.3) 199(-17.425,2.3) 200(-16.575,2.3) 201(-15.725,2.3) 202(-14.875,2.3) 203(-14.025,2.3) 204(-13.175,2.3) 205(-12.325,2.3) 206(-11.475,2.3) 207(-10.625,2.3) 208(-9.775,2.3) 209(-8.925,2.3) 210(-8.075,2.3) 211(-7.225,2.3) 212(-6.375,2.3) 213(-5.525,2.3) 214(-4.675,2.3) 215(-3.825,2.3) 216(-2.975,2.3) 217(-2.125,2.3) 218(-1.275,2.3) 219(-0.425,2.3) 220(0.425,2.3) 221(1.275,2.3) 222(7.225,2.3) 223(8.075,2.3) 224(8.925,2.3) 225(9.775,2.3) 226(10.625,2.3) 227(11.475,2.3) 228(12.325,2.3) 229(13.175,2.3) 230(14.025,2.3) 231(14.875,2.3) 232(15.725,2.3) 233(16.575,2.3) 234(17.425,2.3) 235(18.275,2.3) 236(19.125,2.3) 237(19.975,2.3) 238(20.825,2.3) 239(21.675,2.3) 240(22.525,2.3) 241(23.375,2.3) 242(24.225,2.3) 243(25.075,2.3) 244(25.925,2.3) 245(26.775,2.3) 246(27.625,2.3) 247(28.475,2.3) 248(29.325,2.3) 249(30.175,2.3) 250(31.025,2.3) 251(31.875,2.3) 252(32.725,2.3) 253(33.575,2.3) 254(34.425,2.3) 255(35.275,2.3) 256(36.125,2.3) 257(36.975,2.3) 258(37.825,2.3) 259(38.675,2.3) 260(39.525,2.3) 261(40.375,2.3) 262(41.225,2.3) 263(42.075,2.3) 264(42.925,2.3) 265(43.775,2.3) 266(44.625,2.3) 267(45.475,2.3) 268(46.325,2.3) 269(47.175,2.3) 270(48.025,2.3) 271(48.875,2.3) 272(49.725,2.3) 273(50.575,2.3) 274(51.425,2.3) 275(52.275,2.3) 276(53.125,2.3) 277(53.975,2.3) 278(54.825,2.3) 279(55.675,2.3) 280(56.525,2.3) 281(57.375,2.3) 282(58.225,2.3) 283(59.075,2.3) 284(59.925,2.3) 285(60.775,2.3) 286(61.625,2.3) 287(62.475,2.3) 288(63.325,2.3)
DFN6_EPAD
  rect 0.25x0.7 smd: 1(-0.5,-1.425) 2(0,-1.425) 3(0.5,-1.425) 4(0.5,1.425) 5(0,1.425) 6(-0.5,1.425)
  rect 1.321x1.6 smd: 7(0,0)
DFN8-EPAD_3X2
  rect 0.279x0.787 smd: 1(-0.75,-0.994) 2(-0.25,-0.994) 3(0.25,-0.994) 4(0.75,-0.994) 5(0.75,0.994) 6(0.25,0.994) 7(-0.25,0.994) 8(-0.75,0.994)
  rect 2.21x0.61 smd: 9(0,0)
DFN-10
  rect 0.483x0.787 smd: 1(-1.102,-1.494) 5(1.102,-1.494) 6(1.102,1.494) 10(-1.102,1.494)
  rect 0.279x0.787 smd: 2(-0.5,-1.494) 3(0,-1.494) 4(0.5,-1.494) 7(0.5,1.494) 8(0,1.494) 9(-0.5,1.494)
  rect 2.007x1.524 smd: 11(0,0)
DFN-11
  rect 0.483x0.787 smd: 1(-1.102,-1.494) 5(1.102,-1.494) 6(1.102,1.494) 10(-1.102,1.494)
  rect 0.279x0.787 smd: 2(-0.5,-1.494) 3(0,-1.494) 4(0.5,-1.494) 7(0.5,1.494) 8(0,1.494) 9(-0.5,1.494)
  rect 2.007x1.6 smd: 11(0,0)
DIO_SOD882
  rect 0.4x0.7 smd: 1(-0.35,0) 2(0.35,0)
DIPSWITCH_SMT_QUAD
  rect 0.76x1.27 smd: 1(-1.905,-3.81) 2(-0.635,-3.81) 3(0.635,-3.81) 4(1.905,-3.81) 5(1.905,3.81) 6(0.635,3.81) 7(-0.635,3.81) 8(-1.905,3.81)
DIPSWITCH_SMT_SINGLE
  rect 0.711x0.711 smd: (-1.056,2.156) (-1.056,-2.156) (1.056,2.156) (1.056,-2.156)
  rect 0.711x1.219 smd: 1(0,-2.96) 2(0,2.96)
DRT
  rect 0.305x0.305 smd: 1(-0.35,-0.425) 2(0.35,-0.425) 3(0,0.425)
EG2207
  round 1.778 hole 1.194: (-2.794,-1.003) (6.807,-1.003)
  rect 1.346x1.346 hole 0.787: 1(0,0)
  round 1.346 hole 0.787: 2(2.007,0) 3(4.013,0) 4(0,-2.007) 5(2.007,-2.007) 6(4.013,-2.007)
FBGA2486A_HEX
  round 1.016 smd: (-29,-22.75) (29,22.75)
  round 0.5 smd: (-3.26,3.2) (3.25,-3.2) A6(-22.083,20.5) A8(-20.351,20.5) A10(-18.619,20.5) A12(-16.887,20.5) A14(-15.155,20.5) A16(-13.423,20.5) A18(-11.691,20.5) A20(-9.959,20.5) A22(-8.227,20.5) A24(-6.495,20.5) A26(-4.763,20.5) A28(-3.031,20.5) A30(-1.299,20.5) A32(0.433,20.5) A34(2.165,20.5) A36(3.897,20.5) A38(5.629,20.5) A40(7.361,20.5) A42(9.093,20.5) A44(10.825,20.5) A46(12.557,20.5) A48(14.289,20.5) A50(16.021,20.5) A52(17.753,20.5) A54(19.485,20.5) A56(21.217,20.5) AA2(-25.547,10.5) AA4(-23.815,10.5) AA6(-22.083,10.5) AA8(-20.351,10.5) AA10(-18.619,10.5) AA12(-16.887,10.5) AA14(-15.155,10.5) AA16(-13.423,10.5) AA18(-11.691,10.5) AA20(-9.959,10.5) AA22(-8.227,10.5) AA24(-6.495,10.5) AA26(-4.763,10.5) AA28(-3.031,10.5) AA30(-1.299,10.5) AA32(0.433,10.5) AA34(2.165,10.5) AA36(3.897,10.5) AA38(5.629,10.5) AA40(7.361,10.5) AA42(9.093,10.5) AA44(10.825,10.5) AA46(12.557,10.5) AA48(14.289,10.5) AA50(16.021,10.5) AA52(17.753,10.5) AA54(19.485,10.5) AA56(21.217,10.5) AA58(22.949,10.5) AA60(24.681,10.5) AA62(26.413,10.5) AB1(-26.413,10) AB3(-24.681,10) AB5(-22.949,10) AB7(-21.217,10) AB9(-19.485,10) AB11(-17.753,10) AB13(-16.021,10) AB15(-14.289,10) AB17(-12.557,10) AB19(-10.825,10) AB21(-9.093,10) AB23(-7.361,10) AB25(-5.629,10) AB27(-3.897,10) AB29(-2.165,10) AB31(-0.433,10) AB33(1.299,10) AB35(3.031,10) AB37(4.763,10) AB39(6.495,10) AB41(8.227,10) AB43(9.959,10) AB45(11.691,10) AB47(13.423,10) AB49(15.155,10) AB51(16.887,10) AB53(18.619,10) AB55(20.351,10) AB57(22.083,10) AB59(23.815,10) AB61(25.547,10) AC2(-25.547,9.5) AC4(-23.815,9.5) AC6(-22.083,9.5) AC8(-20.351,9.5) AC10(-18.619,9.5) AC12(-16.887,9.5) AC14(-15.155,9.5) AC16(-13.423,9.5) AC18(-11.691,9.5) AC20(-9.959,9.5) AC22(-8.227,9.5) AC24(-6.495,9.5) AC26(-4.763,9.5) AC28(-3.031,9.5) AC30(-1.299,9.5) AC32(0.433,9.5) AC34(2.165,9.5) AC36(3.897,9.5) AC38(5.629,9.5) AC40(7.361,9.5) AC42(9.093,9.5) AC44(10.825,9.5) AC46(12.557,9.5) AC48(14.289,9.5) AC50(16.021,9.5) AC52(17.753,9.5) AC54(19.485,9.5) AC56(21.217,9.5) AC58(22.949,9.5) AC60(24.681,9.5) AC62(26.413,9.5) AD1(-26.413,9) AD3(-24.681,9) AD5(-22.949,9) AD7(-21.217,9) AD9(-19.485,9) AD11(-17.753,9) AD13(-16.021,9) AD15(-14.289,9) AD17(-12.557,9) AD19(-10.825,9) AD21(-9.093,9) AD23(-7.361,9) AD25(-5.629,9) AD27(-3.897,9) AD29(-2.165,9) AD31(-0.433,9) AD33(1.299,9) AD35(3.031,9) AD37(4.763,9) AD39(6.495,9) AD41(8.227,9) AD43(9.959,9) AD45(11.691,9) AD47(13.423,9) AD49(15.155,9) AD51(16.887,9) AD53(18.619,9) AD55(20.351,9) AD57(22.083,9) AD59(23.815,9) AD61(25.547,9) AE2(-25.547,8.5) AE4(-23.815,8.5) AE6(-22.083,8.5) AE8(-20.351,8.5) AE10(-18.619,8.5) AE12(-16.887,8.5) AE14(-15.155,8.5) AE16(-13.423,8.5) AE18(-11.691,8.5) AE20(-9.959,8.5) AE22(-8.227,8.5) AE24(-6.495,8.5) AE26(-4.763,8.5) AE28(-3.031,8.5) AE30(-1.299,8.5) AE32(0.433,8.5) AE34(2.165,8.5) AE36(3.897,8.5) AE38(5.629,8.5) AE40(7.361,8.5) AE42(9.093,8.5) AE44(10.825,8.5) AE46(12.557,8.5) AE48(14.289,8.5) AE50(16.021,8.5) AE52(17.753,8.5) AE54(19.485,8.5) AE56(21.217,8.5) AE58(22.949,8.5) AE60(24.681,8.5) AE62(26.413,8.5) AF1(-26.413,8) AF3(-24.681,8) AF5(-22.949,8) AF7(-21.217,8) AF9(-19.485,8) AF11(-17.753,8) AF13(-16.021,8) AF15(-14.289,8) AF17(-12.557,8) AF19(-10.825,8) AF21(-9.093,8) AF23(-7.361,8) AF25(-5.629,8) AF27(-3.897,8) AF29(-2.165,8) AF31(-0.433,8) AF33(1.299,8) AF35(3.031,8) AF37(4.763,8) AF39(6.495,8) AF41(8.227,8) AF43(9.959,8) AF45(11.691,8) AF47(13.423,8) AF49(15.155,8) AF51(16.887,8) AF53(18.619,8) AF55(20.351,8) AF57(22.083,8) AF59(23.815,8) AF61(25.547,8) AG2(-25.547,7.5) AG4(-23.815,7.5) AG6(-22.083,7.5) AG8(-20.351,7.5) AG10(-18.619,7.5) AG12(-16.887,7.5) AG14(-15.155,7.5) AG16(-13.423,7.5) AG18(-11.691,7.5) AG20(-9.959,7.5) AG22(-8.227,7.5) AG24(-6.495,7.5) AG26(-4.763,7.5) AG28(-3.031,7.5) AG30(-1.299,7.5) AG32(0.433,7.5) AG34(2.165,7.5) AG36(3.897,7.5) AG38(5.629,7.5) AG40(7.361,7.5) AG42(9.093,7.5) AG44(10.825,7.5) AG46(12.557,7.5) AG48(14.289,7.5) AG50(16.021,7.5) AG52(17.753,7.5) AG54(19.485,7.5) AG56(21.217,7.5) AG58(22.949,7.5) AG60(24.681,7.5) AG62(26.413,7.5) AH1(-26.413,7) AH3(-24.681,7) AH5(-22.949,7) AH7(-21.217,7) AH9(-19.485,7) AH11(-17.753,7) AH13(-16.021,7) AH15(-14.289,7) AH17(-12.557,7) AH19(-10.825,7) AH21(-9.093,7) AH23(-7.361,7) AH25(-5.629,7) AH27(-3.897,7) AH29(-2.165,7) AH31(-0.433,7) AH33(1.299,7) AH35(3.031,7) AH37(4.763,7) AH39(6.495,7) AH41(8.227,7) AH43(9.959,7) AH45(11.691,7) AH47(13.423,7) AH49(15.155,7) AH51(16.887,7) AH53(18.619,7) AH55(20.351,7) AH57(22.083,7) AH59(23.815,7) AH61(25.547,7) AJ2(-25.547,6.5) AJ4(-23.815,6.5) AJ6(-22.083,6.5) AJ8(-20.351,6.5) AJ10(-18.619,6.5) AJ12(-16.887,6.5) AJ14(-15.155,6.5) AJ16(-13.423,6.5) AJ18(-11.691,6.5) AJ20(-9.959,6.5) AJ22(-8.227,6.5) AJ24(-6.495,6.5) AJ26(-4.763,6.5) AJ28(-3.031,6.5) AJ30(-1.299,6.5) AJ32(0.433,6.5) AJ34(2.165,6.5) AJ36(3.897,6.5) AJ38(5.629,6.5) AJ40(7.361,6.5) AJ42(9.093,6.5) AJ44(10.825,6.5) AJ46(12.557,6.5) AJ48(14.289,6.5) AJ50(16.021,6.5) AJ52(17.753,6.5) AJ54(19.485,6.5) AJ56(21.217,6.5) AJ58(22.949,6.5) AJ60(24.681,6.5) AJ62(26.413,6.5) AK1(-26.413,6) AK3(-24.681,6) AK5(-22.949,6) AK7(-21.217,6) AK9(-19.485,6) AK11(-17.753,6) AK13(-16.021,6) AK15(-14.289,6) AK17(-12.557,6) AK19(-10.825,6) AK21(-9.093,6) AK23(-7.361,6) AK25(-5.629,6) AK27(-3.897,6) AK29(-2.165,6) AK31(-0.433,6) AK33(1.299,6) AK35(3.031,6) AK37(4.763,6) AK39(6.495,6) AK41(8.227,6) AK43(9.959,6) AK45(11.691,6) AK47(13.423,6) AK49(15.155,6) AK51(16.887,6) AK53(18.619,6) AK55(20.351,6) AK57(22.083,6) AK59(23.815,6) AK61(25.547,6) AL2(-25.547,5.5) AL4(-23.815,5.5) AL6(-22.083,5.5) AL8(-20.351,5.5) AL10(-18.619,5.5) AL12(-16.887,5.5) AL14(-15.155,5.5) AL16(-13.423,5.5) AL18(-11.691,5.5) AL20(-9.959,5.5) AL22(-8.227,5.5) AL24(-6.495,5.5) AL26(-4.763,5.5) AL28(-3.031,5.5) AL30(-1.299,5.5) AL32(0.433,5.5) AL34(2.165,5.5) AL36(3.897,5.5) AL38(5.629,5.5) AL40(7.361,5.5) AL42(9.093,5.5) AL44(10.825,5.5) AL46(12.557,5.5) AL48(14.289,5.5) AL50(16.021,5.5) AL52(17.753,5.5) AL54(19.485,5.5) AL56(21.217,5.5) AL58(22.949,5.5) AL60(24.681,5.5) AL62(26.413,5.5) AM1(-26.413,5) AM3(-24.681,5) AM5(-22.949,5) AM7(-21.217,5) AM9(-19.485,5) AM11(-17.753,5) AM13(-16.021,5) AM15(-14.289,5) AM17(-12.557,5) AM19(-10.825,5) AM21(-9.093,5) AM23(-7.361,5) AM25(-5.629,5) AM27(-3.897,5) AM29(-2.165,5) AM31(-0.433,5) AM33(1.299,5) AM35(3.031,5) AM37(4.763,5) AM39(6.495,5) AM41(8.227,5) AM43(9.959,5) AM45(11.691,5) AM47(13.423,5) AM49(15.155,5) AM51(16.887,5) AM53(18.619,5) AM55(20.351,5) AM57(22.083,5) AM59(23.815,5) AM61(25.547,5) AN2(-25.547,4.5) AN4(-23.815,4.5) AN6(-22.083,4.5) AN8(-20.351,4.5) AN10(-18.619,4.5) AN12(-16.887,4.5) AN14(-15.155,4.5) AN16(-13.423,4.5) AN18(-11.691,4.5) AN20(-9.959,4.5) AN22(-8.227,4.5) AN24(-6.495,4.5) AN26(-4.763,4.5) AN28(-3.031,4.5) AN30(-1.299,4.5) AN32(0.433,4.5) AN34(2.165,4.5) AN36(3.897,4.5) AN38(5.629,4.5) AN40(7.361,4.5) AN42(9.093,4.5) AN44(10.825,4.5) AN46(12.557,4.5) AN48(14.289,4.5) AN50(16.021,4.5) AN52(17.753,4.5) AN54(19.485,4.5) AN56(21.217,4.5) AN58(22.949,4.5) AN60(24.681,4.5) AN62(26.413,4.5) AP1(-26.413,4) AP3(-24.681,4) AP5(-22.949,4) AP7(-21.217,4) AP9(-19.485,4) AP11(-17.753,4) AP13(-16.021,4) AP15(-14.289,4) AP17(-12.557,4) AP19(-10.825,4) AP21(-9.093,4) AP23(-7.361,4) AP25(-5.629,4) AP37(4.763,4) AP39(6.495,4) AP41(8.227,4) AP43(9.959,4) AP45(11.691,4) AP47(13.423,4) AP49(15.155,4) AP51(16.887,4) AP53(18.619,4) AP55(20.351,4) AP57(22.083,4) AP59(23.815,4) AP61(25.547,4) AR2(-25.547,3.5) AR4(-23.815,3.5) AR6(-22.083,3.5) AR8(-20.351,3.5) AR10(-18.619,3.5) AR12(-16.887,3.5) AR14(-15.155,3.5) AR16(-13.423,3.5) AR18(-11.691,3.5) AR20(-9.959,3.5) AR22(-8.227,3.5) AR24(-6.495,3.5) AR26(-4.763,3.5) AR38(5.629,3.5) AR40(7.361,3.5) AR42(9.093,3.5) AR44(10.825,3.5) AR46(12.557,3.5) AR48(14.289,3.5) AR50(16.021,3.5) AR52(17.753,3.5) AR54(19.485,3.5) AR56(21.217,3.5) AR58(22.949,3.5) AR60(24.681,3.5) AR62(26.413,3.5) AT1(-26.413,3) AT3(-24.681,3) AT5(-22.949,3) AT7(-21.217,3) AT9(-19.485,3) AT11(-17.753,3) AT13(-16.021,3) AT15(-14.289,3) AT17(-12.557,3) AT19(-10.825,3) AT21(-9.093,3) AT23(-7.361,3) AT25(-5.629,3) AT37(4.763,3) AT39(6.495,3) AT41(8.227,3) AT43(9.959,3) AT45(11.691,3) AT47(13.423,3) AT49(15.155,3) AT51(16.887,3) AT53(18.619,3) AT55(20.351,3) AT57(22.083,3) AT59(23.815,3) AT61(25.547,3) AU2(-25.547,2.5) AU4(-23.815,2.5) AU6(-22.083,2.5) AU8(-20.351,2.5) AU10(-18.619,2.5) AU12(-16.887,2.5) AU14(-15.155,2.5) AU16(-13.423,2.5) AU18(-11.691,2.5) AU20(-9.959,2.5) AU22(-8.227,2.5) AU24(-6.495,2.5) AU26(-4.763,2.5) AU38(5.629,2.5) AU40(7.361,2.5) AU42(9.093,2.5) AU44(10.825,2.5) AU46(12.557,2.5) AU48(14.289,2.5) AU50(16.021,2.5) AU52(17.753,2.5) AU54(19.485,2.5) AU56(21.217,2.5) AU58(22.949,2.5) AU60(24.681,2.5) AU62(26.413,2.5) AV1(-26.413,2) AV3(-24.681,2) AV5(-22.949,2) AV7(-21.217,2) AV9(-19.485,2) AV11(-17.753,2) AV13(-16.021,2) AV15(-14.289,2) AV17(-12.557,2) AV19(-10.825,2) AV21(-9.093,2) AV23(-7.361,2) AV25(-5.629,2) AV37(4.763,2) AV39(6.495,2) AV41(8.227,2) AV43(9.959,2) AV45(11.691,2) AV47(13.423,2) AV49(15.155,2) AV51(16.887,2) AV53(18.619,2) AV55(20.351,2) AV57(22.083,2) AV59(23.815,2) AV61(25.547,2) AW2(-25.547,1.5) AW4(-23.815,1.5) AW6(-22.083,1.5) AW8(-20.351,1.5) AW10(-18.619,1.5) AW12(-16.887,1.5) AW14(-15.155,1.5) AW16(-13.423,1.5) AW18(-11.691,1.5) AW20(-9.959,1.5) AW22(-8.227,1.5) AW24(-6.495,1.5) AW26(-4.763,1.5) AW38(5.629,1.5) AW40(7.361,1.5) AW42(9.093,1.5) AW44(10.825,1.5) AW46(12.557,1.5) AW48(14.289,1.5) AW50(16.021,1.5) AW52(17.753,1.5) AW54(19.485,1.5) AW56(21.217,1.5) AW58(22.949,1.5) AW60(24.681,1.5) AW62(26.413,1.5) AY1(-26.413,1) AY3(-24.681,1) AY5(-22.949,1) AY7(-21.217,1) AY9(-19.485,1) AY11(-17.753,1) AY13(-16.021,1) AY15(-14.289,1) AY17(-12.557,1) AY19(-10.825,1) AY21(-9.093,1) AY23(-7.361,1) AY25(-5.629,1) AY37(4.763,1) AY39(6.495,1) AY41(8.227,1) AY43(9.959,1) AY45(11.691,1) AY47(13.423,1) AY49(15.155,1) AY51(16.887,1) AY53(18.619,1) AY55(20.351,1) AY57(22.083,1) AY59(23.815,1) AY61(25.547,1) B5(-22.949,20) B7(-21.217,20) B9(-19.485,20) B11(-17.753,20) B13(-16.021,20) B15(-14.289,20) B17(-12.557,20) B19(-10.825,20) B21(-9.093,20) B23(-7.361,20) B25(-5.629,20) B27(-3.897,20) B29(-2.165,20) B31(-0.433,20) B33(1.299,20) B35(3.031,20) B37(4.763,20) B39(6.495,20) B41(8.227,20) B43(9.959,20) B45(11.691,20) B47(13.423,20) B49(15.155,20) B51(16.887,20) B53(18.619,20) B55(20.351,20) B57(22.083,20) BA2(-25.547,0.5) BA4(-23.815,0.5) BA6(-22.083,0.5) BA8(-20.351,0.5) BA10(-18.619,0.5) BA12(-16.887,0.5) BA14(-15.155,0.5) BA16(-13.423,0.5) BA18(-11.691,0.5) BA20(-9.959,0.5) BA22(-8.227,0.5) BA24(-6.495,0.5) BA26(-4.763,0.5) BA38(5.629,0.5) BA40(7.361,0.5) BA42(9.093,0.5) BA44(10.825,0.5) BA46(12.557,0.5) BA48(14.289,0.5) BA50(16.021,0.5) BA52(17.753,0.5) BA54(19.485,0.5) BA56(21.217,0.5) BA58(22.949,0.5) BA60(24.681,0.5) BA62(26.413,0.5) BB1(-26.413,0) BB3(-24.681,0) BB5(-22.949,0) BB7(-21.217,0) BB9(-19.485,0) BB11(-17.753,0) BB13(-16.021,0) BB15(-14.289,0) BB17(-12.557,0) BB19(-10.825,0) BB21(-9.093,0) BB23(-7.361,0) BB25(-5.629,0) BB37(4.763,0) BB39(6.495,0) BB41(8.227,0) BB43(9.959,0) BB45(11.691,0) BB47(13.423,0) BB49(15.155,0) BB51(16.887,0) BB53(18.619,0) BB55(20.351,0) BB57(22.083,0) BB59(23.815,0) BB61(25.547,0) BC2(-25.547,-0.5) BC4(-23.815,-0.5) BC6(-22.083,-0.5) BC8(-20.351,-0.5) BC10(-18.619,-0.5) BC12(-16.887,-0.5) BC14(-15.155,-0.5) BC16(-13.423,-0.5) BC18(-11.691,-0.5) BC20(-9.959,-0.5) BC22(-8.227,-0.5) BC24(-6.495,-0.5) BC26(-4.763,-0.5) BC38(5.629,-0.5) BC40(7.361,-0.5) BC42(9.093,-0.5) BC44(10.825,-0.5) BC46(12.557,-0.5) BC48(14.289,-0.5) BC50(16.021,-0.5) BC52(17.753,-0.5) BC54(19.485,-0.5) BC56(21.217,-0.5) BC58(22.949,-0.5) BC60(24.681,-0.5) BC62(26.413,-0.5) BD1(-26.413,-1) BD3(-24.681,-1) BD5(-22.949,-1) BD7(-21.217,-1) BD9(-19.485,-1) BD11(-17.753,-1) BD13(-16.021,-1) BD15(-14.289,-1) BD17(-12.557,-1) BD19(-10.825,-1) BD21(-9.093,-1) BD23(-7.361,-1) BD25(-5.629,-1) BD37(4.763,-1) BD39(6.495,-1) BD41(8.227,-1) BD43(9.959,-1) BD45(11.691,-1) BD47(13.423,-1) BD49(15.155,-1) BD51(16.887,-1) BD53(18.619,-1) BD55(20.351,-1) BD57(22.083,-1) BD59(23.815,-1) BD61(25.547,-1) BE2(-25.547,-1.5) BE4(-23.815,-1.5) BE6(-22.083,-1.5) BE8(-20.351,-1.5) BE10(-18.619,-1.5) BE12(-16.887,-1.5) BE14(-15.155,-1.5) BE16(-13.423,-1.5) BE18(-11.691,-1.5) BE20(-9.959,-1.5) BE22(-8.227,-1.5) BE24(-6.495,-1.5) BE26(-4.763,-1.5) BE38(5.629,-1.5) BE40(7.361,-1.5) BE42(9.093,-1.5) BE44(10.825,-1.5) BE46(12.557,-1.5) BE48(14.289,-1.5) BE50(16.021,-1.5) BE52(17.753,-1.5) BE54(19.485,-1.5) BE56(21.217,-1.5) BE58(22.949,-1.5) BE60(24.681,-1.5) BE62(26.413,-1.5) BF1(-26.413,-2) BF3(-24.681,-2) BF5(-22.949,-2) BF7(-21.217,-2) BF9(-19.485,-2) BF11(-17.753,-2) BF13(-16.021,-2) BF15(-14.289,-2) BF17(-12.557,-2) BF19(-10.825,-2) BF21(-9.093,-2) BF23(-7.361,-2) BF25(-5.629,-2) BF37(4.763,-2) BF39(6.495,-2) BF41(8.227,-2) BF43(9.959,-2) BF45(11.691,-2) BF47(13.423,-2) BF49(15.155,-2) BF51(16.887,-2) BF53(18.619,-2) BF55(20.351,-2) BF57(22.083,-2) BF59(23.815,-2) BF61(25.547,-2) BG2(-25.547,-2.5) BG4(-23.815,-2.5) BG6(-22.083,-2.5) BG8(-20.351,-2.5) BG10(-18.619,-2.5) BG12(-16.887,-2.5) BG14(-15.155,-2.5) BG16(-13.423,-2.5) BG18(-11.691,-2.5) BG20(-9.959,-2.5) BG22(-8.227,-2.5) BG24(-6.495,-2.5) BG26(-4.763,-2.5) BG38(5.629,-2.5) BG40(7.361,-2.5) BG42(9.093,-2.5) BG44(10.825,-2.5) BG46(12.557,-2.5) BG48(14.289,-2.5) BG50(16.021,-2.5) BG52(17.753,-2.5) BG54(19.485,-2.5) BG56(21.217,-2.5) BG58(22.949,-2.5) BG60(24.681,-2.5) BG62(26.413,-2.5) BH1(-26.413,-3) BH3(-24.681,-3) BH5(-22.949,-3) BH7(-21.217,-3) BH9(-19.485,-3) BH11(-17.753,-3) BH13(-16.021,-3) BH15(-14.289,-3) BH17(-12.557,-3) BH19(-10.825,-3) BH21(-9.093,-3) BH23(-7.361,-3) BH25(-5.629,-3) BH37(4.763,-3) BH39(6.495,-3) BH41(8.227,-3) BH43(9.959,-3) BH45(11.691,-3) BH47(13.423,-3) BH49(15.155,-3) BH51(16.887,-3) BH53(18.619,-3) BH55(20.351,-3) BH57(22.083,-3) BH59(23.815,-3) BH61(25.547,-3) BJ2(-25.547,-3.5) BJ4(-23.815,-3.5) BJ6(-22.083,-3.5) BJ8(-20.351,-3.5) BJ10(-18.619,-3.5) BJ12(-16.887,-3.5) BJ14(-15.155,-3.5) BJ16(-13.423,-3.5) BJ18(-11.691,-3.5) BJ20(-9.959,-3.5) BJ22(-8.227,-3.5) BJ24(-6.495,-3.5) BJ26(-4.763,-3.5) BJ38(5.629,-3.5) BJ40(7.361,-3.5) BJ42(9.093,-3.5) BJ44(10.825,-3.5) BJ46(12.557,-3.5) BJ48(14.289,-3.5) BJ50(16.021,-3.5) BJ52(17.753,-3.5) BJ54(19.485,-3.5) BJ56(21.217,-3.5) BJ58(22.949,-3.5) BJ60(24.681,-3.5) BJ62(26.413,-3.5) BK1(-26.413,-4) BK3(-24.681,-4) BK5(-22.949,-4) BK7(-21.217,-4) BK9(-19.485,-4) BK11(-17.753,-4) BK13(-16.021,-4) BK15(-14.289,-4) BK17(-12.557,-4) BK19(-10.825,-4) BK21(-9.093,-4) BK23(-7.361,-4) BK25(-5.629,-4) BK37(4.763,-4) BK39(6.495,-4) BK41(8.227,-4) BK43(9.959,-4) BK45(11.691,-4) BK47(13.423,-4) BK49(15.155,-4) BK51(16.887,-4) BK53(18.619,-4) BK55(20.351,-4) BK57(22.083,-4) BK59(23.815,-4) BK61(25.547,-4) BL2(-25.547,-4.5) BL4(-23.815,-4.5) BL6(-22.083,-4.5) BL8(-20.351,-4.5) BL10(-18.619,-4.5) BL12(-16.887,-4.5) BL14(-15.155,-4.5) BL16(-13.423,-4.5) BL18(-11.691,-4.5) BL20(-9.959,-4.5) BL22(-8.227,-4.5) BL24(-6.495,-4.5) BL26(-4.763,-4.5) BL28(-3.031,-4.5) BL30(-1.299,-4.5) BL32(0.433,-4.5) BL34(2.165,-4.5) BL36(3.897,-4.5) BL38(5.629,-4.5) BL40(7.361,-4.5) BL42(9.093,-4.5) BL44(10.825,-4.5) BL46(12.557,-4.5) BL48(14.289,-4.5) BL50(16.021,-4.5) BL52(17.753,-4.5) BL54(19.485,-4.5) BL56(21.217,-4.5) BL58(22.949,-4.5) BL60(24.681,-4.5) BL62(26.413,-4.5) BM1(-26.413,-5) BM3(-24.681,-5) BM5(-22.949,-5) BM7(-21.217,-5) BM9(-19.485,-5) BM11(-17.753,-5) BM13(-16.021,-5) BM15(-14.289,-5) BM17(-12.557,-5) BM19(-10.825,-5) BM21(-9.093,-5) BM23(-7.361,-5) BM25(-5.629,-5) BM27(-3.897,-5) BM29(-2.165,-5) BM31(-0.433,-5) BM33(1.299,-5) BM35(3.031,-5) BM37(4.763,-5) BM39(6.495,-5) BM41(8.227,-5) BM43(9.959,-5) BM45(11.691,-5) BM47(13.423,-5) BM49(15.155,-5) BM51(16.887,-5) BM53(18.619,-5) BM55(20.351,-5) BM57(22.083,-5) BM59(23.815,-5) BM61(25.547,-5) BN2(-25.547,-5.5) BN4(-23.815,-5.5) BN6(-22.083,-5.5) BN8(-20.351,-5.5) BN10(-18.619,-5.5) BN12(-16.887,-5.5) BN14(-15.155,-5.5) BN16(-13.423,-5.5) BN18(-11.691,-5.5) BN20(-9.959,-5.5) BN22(-8.227,-5.5) BN24(-6.495,-5.5) BN26(-4.763,-5.5) BN28(-3.031,-5.5) BN30(-1.299,-5.5) BN32(0.433,-5.5) BN34(2.165,-5.5) BN36(3.897,-5.5) BN38(5.629,-5.5) BN40(7.361,-5.5) BN42(9.093,-5.5) BN44(10.825,-5.5) BN46(12.557,-5.5) BN48(14.289,-5.5) BN50(16.021,-5.5) BN52(17.753,-5.5) BN54(19.485,-5.5) BN56(21.217,-5.5) BN58(22.949,-5.5) BN60(24.681,-5.5) BN62(26.413,-5.5) BP1(-26.413,-6) BP3(-24.681,-6) BP5(-22.949,-6) BP7(-21.217,-6) BP9(-19.485,-6) BP11(-17.753,-6) BP13(-16.021,-6) BP15(-14.289,-6) BP17(-12.557,-6) BP19(-10.825,-6) BP21(-9.093,-6) BP23(-7.361,-6) BP25(-5.629,-6) BP27(-3.897,-6) BP29(-2.165,-6) BP31(-0.433,-6) BP33(1.299,-6) BP35(3.031,-6) BP37(4.763,-6) BP39(6.495,-6) BP41(8.227,-6) BP43(9.959,-6) BP45(11.691,-6) BP47(13.423,-6) BP49(15.155,-6) BP51(16.887,-6) BP53(18.619,-6) BP55(20.351,-6) BP57(22.083,-6) BP59(23.815,-6) BP61(25.547,-6) BR2(-25.547,-6.5) BR4(-23.815,-6.5) BR6(-22.083,-6.5) BR8(-20.351,-6.5) BR10(-18.619,-6.5) BR12(-16.887,-6.5) BR14(-15.155,-6.5) BR16(-13.423,-6.5) BR18(-11.691,-6.5) BR20(-9.959,-6.5) BR22(-8.227,-6.5) BR24(-6.495,-6.5) BR26(-4.763,-6.5) BR28(-3.031,-6.5) BR30(-1.299,-6.5) BR32(0.433,-6.5) BR34(2.165,-6.5) BR36(3.897,-6.5) BR38(5.629,-6.5) BR40(7.361,-6.5) BR42(9.093,-6.5) BR44(10.825,-6.5) BR46(12.557,-6.5) BR48(14.289,-6.5) BR50(16.021,-6.5) BR52(17.753,-6.5) BR54(19.485,-6.5) BR56(21.217,-6.5) BR58(22.949,-6.5) BR60(24.681,-6.5) BR62(26.413,-6.5) BT1(-26.413,-7) BT3(-24.681,-7) BT5(-22.949,-7) BT7(-21.217,-7) BT9(-19.485,-7) BT11(-17.753,-7) BT13(-16.021,-7) BT15(-14.289,-7) BT17(-12.557,-7) BT19(-10.825,-7) BT21(-9.093,-7) BT23(-7.361,-7) BT25(-5.629,-7) BT27(-3.897,-7) BT29(-2.165,-7) BT31(-0.433,-7) BT33(1.299,-7) BT35(3.031,-7) BT37(4.763,-7) BT39(6.495,-7) BT41(8.227,-7) BT43(9.959,-7) BT45(11.691,-7) BT47(13.423,-7) BT49(15.155,-7) BT51(16.887,-7) BT53(18.619,-7) BT55(20.351,-7) BT57(22.083,-7) BT59(23.815,-7) BT61(25.547,-7) BU2(-25.547,-7.5) BU4(-23.815,-7.5) BU6(-22.083,-7.5) BU8(-20.351,-7.5) BU10(-18.619,-7.5) BU12(-16.887,-7.5) BU14(-15.155,-7.5) BU16(-13.423,-7.5) BU18(-11.691,-7.5) BU20(-9.959,-7.5) BU22(-8.227,-7.5) BU24(-6.495,-7.5) BU26(-4.763,-7.5) BU28(-3.031,-7.5) BU30(-1.299,-7.5) BU32(0.433,-7.5) BU34(2.165,-7.5) BU36(3.897,-7.5) BU38(5.629,-7.5) BU40(7.361,-7.5) BU42(9.093,-7.5) BU44(10.825,-7.5) BU46(12.557,-7.5) BU48(14.289,-7.5) BU50(16.021,-7.5) BU52(17.753,-7.5) BU54(19.485,-7.5) BU56(21.217,-7.5) BU58(22.949,-7.5) BU60(24.681,-7.5) BU62(26.413,-7.5) BV1(-26.413,-8) BV3(-24.681,-8) BV5(-22.949,-8) BV7(-21.217,-8) BV9(-19.485,-8) BV11(-17.753,-8) BV13(-16.021,-8) BV15(-14.289,-8) BV17(-12.557,-8) BV19(-10.825,-8) BV21(-9.093,-8) BV23(-7.361,-8) BV25(-5.629,-8) BV27(-3.897,-8) BV29(-2.165,-8) BV31(-0.433,-8) BV33(1.299,-8) BV35(3.031,-8) BV37(4.763,-8) BV39(6.495,-8) BV41(8.227,-8) BV43(9.959,-8) BV45(11.691,-8) BV47(13.423,-8) BV49(15.155,-8) BV51(16.887,-8) BV53(18.619,-8) BV55(20.351,-8) BV57(22.083,-8) BV59(23.815,-8) BV61(25.547,-8) BW2(-25.547,-8.5) BW4(-23.815,-8.5) BW6(-22.083,-8.5) BW8(-20.351,-8.5) BW10(-18.619,-8.5) BW12(-16.887,-8.5) BW14(-15.155,-8.5) BW16(-13.423,-8.5) BW18(-11.691,-8.5) BW20(-9.959,-8.5) BW22(-8.227,-8.5) BW24(-6.495,-8.5) BW26(-4.763,-8.5) BW28(-3.031,-8.5) BW30(-1.299,-8.5) BW32(0.433,-8.5) BW34(2.165,-8.5) BW36(3.897,-8.5) BW38(5.629,-8.5) BW40(7.361,-8.5) BW42(9.093,-8.5) BW44(10.825,-8.5) BW46(12.557,-8.5) BW48(14.289,-8.5) BW50(16.021,-8.5) BW52(17.753,-8.5) BW54(19.485,-8.5) BW56(21.217,-8.5) BW58(22.949,-8.5) BW60(24.681,-8.5) BW62(26.413,-8.5) BY1(-26.413,-9) BY3(-24.681,-9) BY5(-22.949,-9) BY7(-21.217,-9) BY9(-19.485,-9) BY11(-17.753,-9) BY13(-16.021,-9) BY15(-14.289,-9) BY17(-12.557,-9) BY19(-10.825,-9) BY21(-9.093,-9) BY23(-7.361,-9) BY25(-5.629,-9) BY27(-3.897,-9) BY29(-2.165,-9) BY31(-0.433,-9) BY33(1.299,-9) BY35(3.031,-9) BY37(4.763,-9) BY39(6.495,-9) BY41(8.227,-9) BY43(9.959,-9) BY45(11.691,-9) BY47(13.423,-9) BY49(15.155,-9) BY51(16.887,-9) BY53(18.619,-9) BY55(20.351,-9) BY57(22.083,-9) BY59(23.815,-9) BY61(25.547,-9) C4(-23.815,19.5) C6(-22.083,19.5) C8(-20.351,19.5) C10(-18.619,19.5) C12(-16.887,19.5) C14(-15.155,19.5) C16(-13.423,19.5) C18(-11.691,19.5) C20(-9.959,19.5) C22(-8.227,19.5) C24(-6.495,19.5) C26(-4.763,19.5) C28(-3.031,19.5) C30(-1.299,19.5) C32(0.433,19.5) C34(2.165,19.5) C36(3.897,19.5) C38(5.629,19.5) C40(7.361,19.5) C42(9.093,19.5) C44(10.825,19.5) C46(12.557,19.5) C48(14.289,19.5) C50(16.021,19.5) C52(17.753,19.5) C54(19.485,19.5) C56(21.217,19.5) C58(22.949,19.5) CA2(-25.547,-9.5) CA4(-23.815,-9.5) CA6(-22.083,-9.5) CA8(-20.351,-9.5) CA10(-18.619,-9.5) CA12(-16.887,-9.5) CA14(-15.155,-9.5) CA16(-13.423,-9.5) CA18(-11.691,-9.5) CA20(-9.959,-9.5) CA22(-8.227,-9.5) CA24(-6.495,-9.5) CA26(-4.763,-9.5) CA28(-3.031,-9.5) CA30(-1.299,-9.5) CA32(0.433,-9.5) CA34(2.165,-9.5) CA36(3.897,-9.5) CA38(5.629,-9.5) CA40(7.361,-9.5) CA42(9.093,-9.5) CA44(10.825,-9.5) CA46(12.557,-9.5) CA48(14.289,-9.5) CA50(16.021,-9.5) CA52(17.753,-9.5) CA54(19.485,-9.5) CA56(21.217,-9.5) CA58(22.949,-9.5) CA60(24.681,-9.5) CA62(26.413,-9.5) CB1(-26.413,-10) CB3(-24.681,-10) CB5(-22.949,-10) CB7(-21.217,-10) CB9(-19.485,-10) CB11(-17.753,-10) CB13(-16.021,-10) CB15(-14.289,-10) CB17(-12.557,-10) CB19(-10.825,-10) CB21(-9.093,-10) CB23(-7.361,-10) CB25(-5.629,-10) CB27(-3.897,-10) CB29(-2.165,-10) CB31(-0.433,-10) CB33(1.299,-10) CB35(3.031,-10) CB37(4.763,-10) CB39(6.495,-10) CB41(8.227,-10) CB43(9.959,-10) CB45(11.691,-10) CB47(13.423,-10) CB49(15.155,-10) CB51(16.887,-10) CB53(18.619,-10) CB55(20.351,-10) CB57(22.083,-10) CB59(23.815,-10) CB61(25.547,-10) CC2(-25.547,-10.5) CC4(-23.815,-10.5) CC6(-22.083,-10.5) CC8(-20.351,-10.5) CC10(-18.619,-10.5) CC12(-16.887,-10.5) CC14(-15.155,-10.5) CC16(-13.423,-10.5) CC18(-11.691,-10.5) CC20(-9.959,-10.5) CC22(-8.227,-10.5) CC24(-6.495,-10.5) CC26(-4.763,-10.5) CC28(-3.031,-10.5) CC30(-1.299,-10.5) CC32(0.433,-10.5) CC34(2.165,-10.5) CC36(3.897,-10.5) CC38(5.629,-10.5) CC40(7.361,-10.5) CC42(9.093,-10.5) CC44(10.825,-10.5) CC46(12.557,-10.5) CC48(14.289,-10.5) CC50(16.021,-10.5) CC52(17.753,-10.5) CC54(19.485,-10.5) CC56(21.217,-10.5) CC58(22.949,-10.5) CC60(24.681,-10.5) CC62(26.413,-10.5) CD1(-26.413,-11) CD3(-24.681,-11) CD5(-22.949,-11) CD7(-21.217,-11) CD9(-19.485,-11) CD11(-17.753,-11) CD13(-16.021,-11) CD15(-14.289,-11) CD17(-12.557,-11) CD19(-10.825,-11) CD21(-9.093,-11) CD23(-7.361,-11) CD25(-5.629,-11) CD27(-3.897,-11) CD29(-2.165,-11) CD31(-0.433,-11) CD33(1.299,-11) CD35(3.031,-11) CD37(4.763,-11) CD39(6.495,-11) CD41(8.227,-11) CD43(9.959,-11) CD45(11.691,-11) CD47(13.423,-11) CD49(15.155,-11) CD51(16.887,-11) CD53(18.619,-11) CD55(20.351,-11) CD57(22.083,-11) CD59(23.815,-11) CD61(25.547,-11) CE2(-25.547,-11.5) CE4(-23.815,-11.5) CE6(-22.083,-11.5) CE8(-20.351,-11.5) CE10(-18.619,-11.5) CE12(-16.887,-11.5) CE14(-15.155,-11.5) CE16(-13.423,-11.5) CE18(-11.691,-11.5) CE20(-9.959,-11.5) CE22(-8.227,-11.5) CE24(-6.495,-11.5) CE26(-4.763,-11.5) CE28(-3.031,-11.5) CE30(-1.299,-11.5) CE32(0.433,-11.5) CE34(2.165,-11.5) CE36(3.897,-11.5) CE38(5.629,-11.5) CE40(7.361,-11.5) CE42(9.093,-11.5) CE44(10.825,-11.5) CE46(12.557,-11.5) CE48(14.289,-11.5) CE50(16.021,-11.5) CE52(17.753,-11.5) CE54(19.485,-11.5) CE56(21.217,-11.5) CE58(22.949,-11.5) CE60(24.681,-11.5) CE62(26.413,-11.5) CF1(-26.413,-12) CF3(-24.681,-12) CF5(-22.949,-12) CF7(-21.217,-12) CF9(-19.485,-12) CF11(-17.753,-12) CF13(-16.021,-12) CF15(-14.289,-12) CF17(-12.557,-12) CF19(-10.825,-12) CF21(-9.093,-12) CF23(-7.361,-12) CF25(-5.629,-12) CF27(-3.897,-12) CF29(-2.165,-12) CF31(-0.433,-12) CF33(1.299,-12) CF35(3.031,-12) CF37(4.763,-12) CF39(6.495,-12) CF41(8.227,-12) CF43(9.959,-12) CF45(11.691,-12) CF47(13.423,-12) CF49(15.155,-12) CF51(16.887,-12) CF53(18.619,-12) CF55(20.351,-12) CF57(22.083,-12) CF59(23.815,-12) CF61(25.547,-12) CG2(-25.547,-12.5) CG4(-23.815,-12.5) CG6(-22.083,-12.5) CG8(-20.351,-12.5) CG10(-18.619,-12.5) CG12(-16.887,-12.5) CG14(-15.155,-12.5) CG16(-13.423,-12.5) CG18(-11.691,-12.5) CG20(-9.959,-12.5) CG22(-8.227,-12.5) CG24(-6.495,-12.5) CG26(-4.763,-12.5) CG28(-3.031,-12.5) CG30(-1.299,-12.5) CG32(0.433,-12.5) CG34(2.165,-12.5) CG36(3.897,-12.5) CG38(5.629,-12.5) CG40(7.361,-12.5) CG42(9.093,-12.5) CG44(10.825,-12.5) CG46(12.557,-12.5) CG48(14.289,-12.5) CG50(16.021,-12.5) CG52(17.753,-12.5) CG54(19.485,-12.5) CG56(21.217,-12.5) CG58(22.949,-12.5) CG60(24.681,-12.5) CG62(26.413,-12.5) CH1(-26.413,-13) CH3(-24.681,-13) CH5(-22.949,-13) CH7(-21.217,-13) CH9(-19.485,-13) CH11(-17.753,-13) CH13(-16.021,-13) CH15(-14.289,-13) CH17(-12.557,-13) CH19(-10.825,-13) CH21(-9.093,-13) CH23(-7.361,-13) CH25(-5.629,-13) CH27(-3.897,-13) CH29(-2.165,-13) CH31(-0.433,-13) CH33(1.299,-13) CH35(3.031,-13) CH37(4.763,-13) CH39(6.495,-13) CH41(8.227,-13) CH43(9.959,-13) CH45(11.691,-13) CH47(13.423,-13) CH49(15.155,-13) CH51(16.887,-13) CH53(18.619,-13) CH55(20.351,-13) CH57(22.083,-13) CH59(23.815,-13) CH61(25.547,-13) CJ2(-25.547,-13.5) CJ4(-23.815,-13.5) CJ6(-22.083,-13.5) CJ8(-20.351,-13.5) CJ10(-18.619,-13.5) CJ12(-16.887,-13.5) CJ14(-15.155,-13.5) CJ16(-13.423,-13.5) CJ18(-11.691,-13.5) CJ20(-9.959,-13.5) CJ22(-8.227,-13.5) CJ24(-6.495,-13.5) CJ26(-4.763,-13.5) CJ28(-3.031,-13.5) CJ30(-1.299,-13.5) CJ32(0.433,-13.5) CJ34(2.165,-13.5) CJ36(3.897,-13.5) CJ38(5.629,-13.5) CJ40(7.361,-13.5) CJ42(9.093,-13.5) CJ44(10.825,-13.5) CJ46(12.557,-13.5) CJ48(14.289,-13.5) CJ50(16.021,-13.5) CJ52(17.753,-13.5) CJ54(19.485,-13.5) CJ56(21.217,-13.5) CJ58(22.949,-13.5) CJ60(24.681,-13.5) CJ62(26.413,-13.5) CK1(-26.413,-14) CK3(-24.681,-14) CK5(-22.949,-14) CK7(-21.217,-14) CK9(-19.485,-14) CK11(-17.753,-14) CK13(-16.021,-14) CK15(-14.289,-14) CK17(-12.557,-14) CK19(-10.825,-14) CK21(-9.093,-14) CK23(-7.361,-14) CK25(-5.629,-14) CK27(-3.897,-14) CK29(-2.165,-14) CK31(-0.433,-14) CK33(1.299,-14) CK35(3.031,-14) CK37(4.763,-14) CK39(6.495,-14) CK41(8.227,-14) CK43(9.959,-14) CK45(11.691,-14) CK47(13.423,-14) CK49(15.155,-14) CK51(16.887,-14) CK53(18.619,-14) CK55(20.351,-14) CK57(22.083,-14) CK59(23.815,-14) CK61(25.547,-14) CL2(-25.547,-14.5) CL4(-23.815,-14.5) CL6(-22.083,-14.5) CL8(-20.351,-14.5) CL10(-18.619,-14.5) CL12(-16.887,-14.5) CL14(-15.155,-14.5) CL16(-13.423,-14.5) CL18(-11.691,-14.5) CL20(-9.959,-14.5) CL22(-8.227,-14.5) CL24(-6.495,-14.5) CL26(-4.763,-14.5) CL28(-3.031,-14.5) CL30(-1.299,-14.5) CL32(0.433,-14.5) CL34(2.165,-14.5) CL36(3.897,-14.5) CL38(5.629,-14.5) CL40(7.361,-14.5) CL42(9.093,-14.5) CL44(10.825,-14.5) CL46(12.557,-14.5) CL48(14.289,-14.5) CL50(16.021,-14.5) CL52(17.753,-14.5) CL54(19.485,-14.5) CL56(21.217,-14.5) CL58(22.949,-14.5) CL60(24.681,-14.5) CL62(26.413,-14.5) CM1(-26.413,-15) CM3(-24.681,-15) CM5(-22.949,-15) CM7(-21.217,-15) CM9(-19.485,-15) CM11(-17.753,-15) CM13(-16.021,-15) CM15(-14.289,-15) CM17(-12.557,-15) CM19(-10.825,-15) CM21(-9.093,-15) CM23(-7.361,-15) CM25(-5.629,-15) CM27(-3.897,-15) CM29(-2.165,-15) CM31(-0.433,-15) CM33(1.299,-15) CM35(3.031,-15) CM37(4.763,-15) CM39(6.495,-15) CM41(8.227,-15) CM43(9.959,-15) CM45(11.691,-15) CM47(13.423,-15) CM49(15.155,-15) CM51(16.887,-15) CM53(18.619,-15) CM55(20.351,-15) CM57(22.083,-15) CM59(23.815,-15) CM61(25.547,-15) CN2(-25.547,-15.5) CN4(-23.815,-15.5) CN6(-22.083,-15.5) CN8(-20.351,-15.5) CN10(-18.619,-15.5) CN12(-16.887,-15.5) CN14(-15.155,-15.5) CN16(-13.423,-15.5) CN18(-11.691,-15.5) CN20(-9.959,-15.5) CN22(-8.227,-15.5) CN24(-6.495,-15.5) CN26(-4.763,-15.5) CN28(-3.031,-15.5) CN30(-1.299,-15.5) CN32(0.433,-15.5) CN34(2.165,-15.5) CN36(3.897,-15.5) CN38(5.629,-15.5) CN40(7.361,-15.5) CN42(9.093,-15.5) CN44(10.825,-15.5) CN46(12.557,-15.5) CN48(14.289,-15.5) CN50(16.021,-15.5) CN52(17.753,-15.5) CN54(19.485,-15.5) CN56(21.217,-15.5) CN58(22.949,-15.5) CN60(24.681,-15.5) CN62(26.413,-15.5) CP1(-26.413,-16) CP3(-24.681,-16) CP5(-22.949,-16) CP7(-21.217,-16) CP9(-19.485,-16) CP11(-17.753,-16) CP13(-16.021,-16) CP15(-14.289,-16) CP17(-12.557,-16) CP19(-10.825,-16) CP21(-9.093,-16) CP23(-7.361,-16) CP25(-5.629,-16) CP27(-3.897,-16) CP29(-2.165,-16) CP31(-0.433,-16) CP33(1.299,-16) CP35(3.031,-16) CP37(4.763,-16) CP39(6.495,-16) CP41(8.227,-16) CP43(9.959,-16) CP45(11.691,-16) CP47(13.423,-16) CP49(15.155,-16) CP51(16.887,-16) CP53(18.619,-16) CP55(20.351,-16) CP57(22.083,-16) CP59(23.815,-16) CP61(25.547,-16) CR2(-25.547,-16.5) CR4(-23.815,-16.5) CR6(-22.083,-16.5) CR8(-20.351,-16.5) CR10(-18.619,-16.5) CR12(-16.887,-16.5) CR14(-15.155,-16.5) CR16(-13.423,-16.5) CR18(-11.691,-16.5) CR20(-9.959,-16.5) CR22(-8.227,-16.5) CR24(-6.495,-16.5) CR26(-4.763,-16.5) CR28(-3.031,-16.5) CR30(-1.299,-16.5) CR32(0.433,-16.5) CR34(2.165,-16.5) CR36(3.897,-16.5) CR38(5.629,-16.5) CR40(7.361,-16.5) CR42(9.093,-16.5) CR44(10.825,-16.5) CR46(12.557,-16.5) CR48(14.289,-16.5) CR50(16.021,-16.5) CR52(17.753,-16.5) CR54(19.485,-16.5) CR56(21.217,-16.5) CR58(22.949,-16.5) CR60(24.681,-16.5) CR62(26.413,-16.5) CT1(-26.413,-17) CT3(-24.681,-17) CT5(-22.949,-17) CT7(-21.217,-17) CT9(-19.485,-17) CT11(-17.753,-17) CT13(-16.021,-17) CT15(-14.289,-17) CT17(-12.557,-17) CT19(-10.825,-17) CT21(-9.093,-17) CT23(-7.361,-17) CT25(-5.629,-17) CT27(-3.897,-17) CT29(-2.165,-17) CT31(-0.433,-17) CT33(1.299,-17) CT35(3.031,-17) CT37(4.763,-17) CT39(6.495,-17) CT41(8.227,-17) CT43(9.959,-17) CT45(11.691,-17) CT47(13.423,-17) CT49(15.155,-17) CT51(16.887,-17) CT53(18.619,-17) CT55(20.351,-17) CT57(22.083,-17) CT59(23.815,-17) CT61(25.547,-17) CU2(-25.547,-17.5) CU4(-23.815,-17.5) CU6(-22.083,-17.5) CU8(-20.351,-17.5) CU10(-18.619,-17.5) CU12(-16.887,-17.5) CU14(-15.155,-17.5) CU16(-13.423,-17.5) CU18(-11.691,-17.5) CU20(-9.959,-17.5) CU22(-8.227,-17.5) CU24(-6.495,-17.5) CU26(-4.763,-17.5) CU28(-3.031,-17.5) CU30(-1.299,-17.5) CU32(0.433,-17.5) CU34(2.165,-17.5) CU36(3.897,-17.5) CU38(5.629,-17.5) CU40(7.361,-17.5) CU42(9.093,-17.5) CU44(10.825,-17.5) CU46(12.557,-17.5) CU48(14.289,-17.5) CU50(16.021,-17.5) CU52(17.753,-17.5) CU54(19.485,-17.5) CU56(21.217,-17.5) CU58(22.949,-17.5) CU60(24.681,-17.5) CU62(26.413,-17.5) CV1(-26.413,-18) CV3(-24.681,-18) CV5(-22.949,-18) CV7(-21.217,-18) CV9(-19.485,-18) CV11(-17.753,-18) CV13(-16.021,-18) CV15(-14.289,-18) CV17(-12.557,-18) CV19(-10.825,-18) CV21(-9.093,-18) CV23(-7.361,-18) CV25(-5.629,-18) CV27(-3.897,-18) CV29(-2.165,-18) CV31(-0.433,-18) CV33(1.299,-18) CV35(3.031,-18) CV37(4.763,-18) CV39(6.495,-18) CV41(8.227,-18) CV43(9.959,-18) CV45(11.691,-18) CV47(13.423,-18) CV49(15.155,-18) CV51(16.887,-18) CV53(18.619,-18) CV55(20.351,-18) CV57(22.083,-18) CV59(23.815,-18) CV61(25.547,-18) CW2(-25.547,-18.5) CW4(-23.815,-18.5) CW6(-22.083,-18.5) CW8(-20.351,-18.5) CW10(-18.619,-18.5) CW12(-16.887,-18.5) CW14(-15.155,-18.5) CW16(-13.423,-18.5) CW18(-11.691,-18.5) CW20(-9.959,-18.5) CW22(-8.227,-18.5) CW24(-6.495,-18.5) CW26(-4.763,-18.5) CW28(-3.031,-18.5) CW30(-1.299,-18.5) CW32(0.433,-18.5) CW34(2.165,-18.5) CW36(3.897,-18.5) CW38(5.629,-18.5) CW40(7.361,-18.5) CW42(9.093,-18.5) CW44(10.825,-18.5) CW46(12.557,-18.5) CW48(14.289,-18.5) CW50(16.021,-18.5) CW52(17.753,-18.5) CW54(19.485,-18.5) CW56(21.217,-18.5) CW58(22.949,-18.5) CW60(24.681,-18.5) CY3(-24.681,-19) CY5(-22.949,-19) CY7(-21.217,-19) CY9(-19.485,-19) CY11(-17.753,-19) CY13(-16.021,-19) CY15(-14.289,-19) CY17(-12.557,-19) CY19(-10.825,-19) CY21(-9.093,-19) CY23(-7.361,-19) CY25(-5.629,-19) CY27(-3.897,-19) CY29(-2.165,-19) CY31(-0.433,-19) CY33(1.299,-19) CY35(3.031,-19) CY37(4.763,-19) CY39(6.495,-19) CY41(8.227,-19) CY43(9.959,-19) CY45(11.691,-19) CY47(13.423,-19) CY49(15.155,-19) CY51(16.887,-19) CY53(18.619,-19) CY55(20.351,-19) CY57(22.083,-19) CY59(23.815,-19) D3(-24.681,19) D5(-22.949,19) D7(-21.217,19) D9(-19.485,19) D11(-17.753,19) D13(-16.021,19) D15(-14.289,19) D17(-12.557,19) D19(-10.825,19) D21(-9.093,19) D23(-7.361,19) D25(-5.629,19) D27(-3.897,19) D29(-2.165,19) D31(-0.433,19) D33(1.299,19) D35(3.031,19) D37(4.763,19) D39(6.495,19) D41(8.227,19) D43(9.959,19) D45(11.691,19) D47(13.423,19) D49(15.155,19) D51(16.887,19) D53(18.619,19) D55(20.351,19) D57(22.083,19) D59(23.815,19) DA4(-23.815,-19.5) DA6(-22.083,-19.5) DA8(-20.351,-19.5) DA10(-18.619,-19.5) DA12(-16.887,-19.5) DA14(-15.155,-19.5) DA16(-13.423,-19.5) DA18(-11.691,-19.5) DA20(-9.959,-19.5) DA22(-8.227,-19.5) DA24(-6.495,-19.5) DA26(-4.763,-19.5) DA28(-3.031,-19.5) DA30(-1.299,-19.5) DA32(0.433,-19.5) DA34(2.165,-19.5) DA36(3.897,-19.5) DA38(5.629,-19.5) DA40(7.361,-19.5) DA42(9.093,-19.5) DA44(10.825,-19.5) DA46(12.557,-19.5) DA48(14.289,-19.5) DA50(16.021,-19.5) DA52(17.753,-19.5) DA54(19.485,-19.5) DA56(21.217,-19.5) DA58(22.949,-19.5) DB5(-22.949,-20) DB7(-21.217,-20) DB9(-19.485,-20) DB11(-17.753,-20) DB13(-16.021,-20) DB15(-14.289,-20) DB17(-12.557,-20) DB19(-10.825,-20) DB21(-9.093,-20) DB23(-7.361,-20) DB25(-5.629,-20) DB27(-3.897,-20) DB29(-2.165,-20) DB31(-0.433,-20) DB33(1.299,-20) DB35(3.031,-20) DB37(4.763,-20) DB39(6.495,-20) DB41(8.227,-20) DB43(9.959,-20) DB45(11.691,-20) DB47(13.423,-20) DB49(15.155,-20) DB51(16.887,-20) DB53(18.619,-20) DB55(20.351,-20) DB57(22.083,-20) DC6(-22.083,-20.5) DC8(-20.351,-20.5) DC10(-18.619,-20.5) DC12(-16.887,-20.5) DC14(-15.155,-20.5) DC16(-13.423,-20.5) DC18(-11.691,-20.5) DC20(-9.959,-20.5) DC22(-8.227,-20.5) DC24(-6.495,-20.5) DC26(-4.763,-20.5) DC28(-3.031,-20.5) DC30(-1.299,-20.5) DC32(0.433,-20.5) DC34(2.165,-20.5) DC36(3.897,-20.5) DC38(5.629,-20.5) DC40(7.361,-20.5) DC42(9.093,-20.5) DC44(10.825,-20.5) DC46(12.557,-20.5) DC48(14.289,-20.5) DC50(16.021,-20.5) DC52(17.753,-20.5) DC54(19.485,-20.5) DC56(21.217,-20.5) E2(-25.547,18.5) E4(-23.815,18.5) E6(-22.083,18.5) E8(-20.351,18.5) E10(-18.619,18.5) E12(-16.887,18.5) E14(-15.155,18.5) E16(-13.423,18.5) E18(-11.691,18.5) E20(-9.959,18.5) E22(-8.227,18.5) E24(-6.495,18.5) E26(-4.763,18.5) E28(-3.031,18.5) E30(-1.299,18.5) E32(0.433,18.5) E34(2.165,18.5) E36(3.897,18.5) E38(5.629,18.5) E40(7.361,18.5) E42(9.093,18.5) E44(10.825,18.5) E46(12.557,18.5) E48(14.289,18.5) E50(16.021,18.5) E52(17.753,18.5) E54(19.485,18.5) E56(21.217,18.5) E58(22.949,18.5) E60(24.681,18.5) F1(-26.413,18) F3(-24.681,18) F5(-22.949,18) F7(-21.217,18) F9(-19.485,18) F11(-17.753,18) F13(-16.021,18) F15(-14.289,18) F17(-12.557,18) F19(-10.825,18) F21(-9.093,18) F23(-7.361,18) F25(-5.629,18) F27(-3.897,18) F29(-2.165,18) F31(-0.433,18) F33(1.299,18) F35(3.031,18) F37(4.763,18) F39(6.495,18) F41(8.227,18) F43(9.959,18) F45(11.691,18) F47(13.423,18) F49(15.155,18) F51(16.887,18) F53(18.619,18) F55(20.351,18) F57(22.083,18) F59(23.815,18) F61(25.547,18) G2(-25.547,17.5) G4(-23.815,17.5) G6(-22.083,17.5) G8(-20.351,17.5) G10(-18.619,17.5) G12(-16.887,17.5) G14(-15.155,17.5) G16(-13.423,17.5) G18(-11.691,17.5) G20(-9.959,17.5) G22(-8.227,17.5) G24(-6.495,17.5) G26(-4.763,17.5) G28(-3.031,17.5) G30(-1.299,17.5) G32(0.433,17.5) G34(2.165,17.5) G36(3.897,17.5) G38(5.629,17.5) G40(7.361,17.5) G42(9.093,17.5) G44(10.825,17.5) G46(12.557,17.5) G48(14.289,17.5) G50(16.021,17.5) G52(17.753,17.5) G54(19.485,17.5) G56(21.217,17.5) G58(22.949,17.5) G60(24.681,17.5) G62(26.413,17.5) H1(-26.413,17) H3(-24.681,17) H5(-22.949,17) H7(-21.217,17) H9(-19.485,17) H11(-17.753,17) H13(-16.021,17) H15(-14.289,17) H17(-12.557,17) H19(-10.825,17) H21(-9.093,17) H23(-7.361,17) H25(-5.629,17) H27(-3.897,17) H29(-2.165,17) H31(-0.433,17) H33(1.299,17) H35(3.031,17) H37(4.763,17) H39(6.495,17) H41(8.227,17) H43(9.959,17) H45(11.691,17) H47(13.423,17) H49(15.155,17) H51(16.887,17) H53(18.619,17) H55(20.351,17) H57(22.083,17) H59(23.815,17) H61(25.547,17) J2(-25.547,16.5) J4(-23.815,16.5) J6(-22.083,16.5) J8(-20.351,16.5) J10(-18.619,16.5) J12(-16.887,16.5) J14(-15.155,16.5) J16(-13.423,16.5) J18(-11.691,16.5) J20(-9.959,16.5) J22(-8.227,16.5) J24(-6.495,16.5) J26(-4.763,16.5) J28(-3.031,16.5) J30(-1.299,16.5) J32(0.433,16.5) J34(2.165,16.5) J36(3.897,16.5) J38(5.629,16.5) J40(7.361,16.5) J42(9.093,16.5) J44(10.825,16.5) J46(12.557,16.5) J48(14.289,16.5) J50(16.021,16.5) J52(17.753,16.5) J54(19.485,16.5) J56(21.217,16.5) J58(22.949,16.5) J60(24.681,16.5) J62(26.413,16.5) K1(-26.413,16) K3(-24.681,16) K5(-22.949,16) K7(-21.217,16) K9(-19.485,16) K11(-17.753,16) K13(-16.021,16) K15(-14.289,16) K17(-12.557,16) K19(-10.825,16) K21(-9.093,16) K23(-7.361,16) K25(-5.629,16) K27(-3.897,16) K29(-2.165,16) K31(-0.433,16) K33(1.299,16) K35(3.031,16) K37(4.763,16) K39(6.495,16) K41(8.227,16) K43(9.959,16) K45(11.691,16) K47(13.423,16) K49(15.155,16) K51(16.887,16) K53(18.619,16) K55(20.351,16) K57(22.083,16) K59(23.815,16) K61(25.547,16) L2(-25.547,15.5) L4(-23.815,15.5) L6(-22.083,15.5) L8(-20.351,15.5) L10(-18.619,15.5) L12(-16.887,15.5) L14(-15.155,15.5) L16(-13.423,15.5) L18(-11.691,15.5) L20(-9.959,15.5) L22(-8.227,15.5) L24(-6.495,15.5) L26(-4.763,15.5) L28(-3.031,15.5) L30(-1.299,15.5) L32(0.433,15.5) L34(2.165,15.5) L36(3.897,15.5) L38(5.629,15.5) L40(7.361,15.5) L42(9.093,15.5) L44(10.825,15.5) L46(12.557,15.5) L48(14.289,15.5) L50(16.021,15.5) L52(17.753,15.5) L54(19.485,15.5) L56(21.217,15.5) L58(22.949,15.5) L60(24.681,15.5) L62(26.413,15.5) M1(-26.413,15) M3(-24.681,15) M5(-22.949,15) M7(-21.217,15) M9(-19.485,15) M11(-17.753,15) M13(-16.021,15) M15(-14.289,15) M17(-12.557,15) M19(-10.825,15) M21(-9.093,15) M23(-7.361,15) M25(-5.629,15) M27(-3.897,15) M29(-2.165,15) M31(-0.433,15) M33(1.299,15) M35(3.031,15) M37(4.763,15) M39(6.495,15) M41(8.227,15) M43(9.959,15) M45(11.691,15) M47(13.423,15) M49(15.155,15) M51(16.887,15) M53(18.619,15) M55(20.351,15) M57(22.083,15) M59(23.815,15) M61(25.547,15) N2(-25.547,14.5) N4(-23.815,14.5) N6(-22.083,14.5) N8(-20.351,14.5) N10(-18.619,14.5) N12(-16.887,14.5) N14(-15.155,14.5) N16(-13.423,14.5) N18(-11.691,14.5) N20(-9.959,14.5) N22(-8.227,14.5) N24(-6.495,14.5) N26(-4.763,14.5) N28(-3.031,14.5) N30(-1.299,14.5) N32(0.433,14.5) N34(2.165,14.5) N36(3.897,14.5) N38(5.629,14.5) N40(7.361,14.5) N42(9.093,14.5) N44(10.825,14.5) N46(12.557,14.5) N48(14.289,14.5) N50(16.021,14.5) N52(17.753,14.5) N54(19.485,14.5) N56(21.217,14.5) N58(22.949,14.5) N60(24.681,14.5) N62(26.413,14.5) P1(-26.413,14) P3(-24.681,14) P5(-22.949,14) P7(-21.217,14) P9(-19.485,14) P11(-17.753,14) P13(-16.021,14) P15(-14.289,14) P17(-12.557,14) P19(-10.825,14) P21(-9.093,14) P23(-7.361,14) P25(-5.629,14) P27(-3.897,14) P29(-2.165,14) P31(-0.433,14) P33(1.299,14) P35(3.031,14) P37(4.763,14) P39(6.495,14) P41(8.227,14) P43(9.959,14) P45(11.691,14) P47(13.423,14) P49(15.155,14) P51(16.887,14) P53(18.619,14) P55(20.351,14) P57(22.083,14) P59(23.815,14) P61(25.547,14) R2(-25.547,13.5) R4(-23.815,13.5) R6(-22.083,13.5) R8(-20.351,13.5) R10(-18.619,13.5) R12(-16.887,13.5) R14(-15.155,13.5) R16(-13.423,13.5) R18(-11.691,13.5) R20(-9.959,13.5) R22(-8.227,13.5) R24(-6.495,13.5) R26(-4.763,13.5) R28(-3.031,13.5) R30(-1.299,13.5) R32(0.433,13.5) R34(2.165,13.5) R36(3.897,13.5) R38(5.629,13.5) R40(7.361,13.5) R42(9.093,13.5) R44(10.825,13.5) R46(12.557,13.5) R48(14.289,13.5) R50(16.021,13.5) R52(17.753,13.5) R54(19.485,13.5) R56(21.217,13.5) R58(22.949,13.5) R60(24.681,13.5) R62(26.413,13.5) T1(-26.413,13) T3(-24.681,13) T5(-22.949,13) T7(-21.217,13) T9(-19.485,13) T11(-17.753,13) T13(-16.021,13) T15(-14.289,13) T17(-12.557,13) T19(-10.825,13) T21(-9.093,13) T23(-7.361,13) T25(-5.629,13) T27(-3.897,13) T29(-2.165,13) T31(-0.433,13) T33(1.299,13) T35(3.031,13) T37(4.763,13) T39(6.495,13) T41(8.227,13) T43(9.959,13) T45(11.691,13) T47(13.423,13) T49(15.155,13) T51(16.887,13) T53(18.619,13) T55(20.351,13) T57(22.083,13) T59(23.815,13) T61(25.547,13) U2(-25.547,12.5) U4(-23.815,12.5) U6(-22.083,12.5) U8(-20.351,12.5) U10(-18.619,12.5) U12(-16.887,12.5) U14(-15.155,12.5) U16(-13.423,12.5) U18(-11.691,12.5) U20(-9.959,12.5) U22(-8.227,12.5) U24(-6.495,12.5) U26(-4.763,12.5) U28(-3.031,12.5) U30(-1.299,12.5) U32(0.433,12.5) U34(2.165,12.5) U36(3.897,12.5) U38(5.629,12.5) U40(7.361,12.5) U42(9.093,12.5) U44(10.825,12.5) U46(12.557,12.5) U48(14.289,12.5) U50(16.021,12.5) U52(17.753,12.5) U54(19.485,12.5) U56(21.217,12.5) U58(22.949,12.5) U60(24.681,12.5) U62(26.413,12.5) V1(-26.413,12) V3(-24.681,12) V5(-22.949,12) V7(-21.217,12) V9(-19.485,12) V11(-17.753,12) V13(-16.021,12) V15(-14.289,12) V17(-12.557,12) V19(-10.825,12) V21(-9.093,12) V23(-7.361,12) V25(-5.629,12) V27(-3.897,12) V29(-2.165,12) V31(-0.433,12) V33(1.299,12) V35(3.031,12) V37(4.763,12) V39(6.495,12) V41(8.227,12) V43(9.959,12) V45(11.691,12) V47(13.423,12) V49(15.155,12) V51(16.887,12) V53(18.619,12) V55(20.351,12) V57(22.083,12) V59(23.815,12) V61(25.547,12) W2(-25.547,11.5) W4(-23.815,11.5) W6(-22.083,11.5) W8(-20.351,11.5) W10(-18.619,11.5) W12(-16.887,11.5) W14(-15.155,11.5) W16(-13.423,11.5) W18(-11.691,11.5) W20(-9.959,11.5) W22(-8.227,11.5) W24(-6.495,11.5) W26(-4.763,11.5) W28(-3.031,11.5) W30(-1.299,11.5) W32(0.433,11.5) W34(2.165,11.5) W36(3.897,11.5) W38(5.629,11.5) W40(7.361,11.5) W42(9.093,11.5) W44(10.825,11.5) W46(12.557,11.5) W48(14.289,11.5) W50(16.021,11.5) W52(17.753,11.5) W54(19.485,11.5) W56(21.217,11.5) W58(22.949,11.5) W60(24.681,11.5) W62(26.413,11.5) Y1(-26.413,11) Y3(-24.681,11) Y5(-22.949,11) Y7(-21.217,11) Y9(-19.485,11) Y11(-17.753,11) Y13(-16.021,11) Y15(-14.289,11) Y17(-12.557,11) Y19(-10.825,11) Y21(-9.093,11) Y23(-7.361,11) Y25(-5.629,11) Y27(-3.897,11) Y29(-2.165,11) Y31(-0.433,11) Y33(1.299,11) Y35(3.031,11) Y37(4.763,11) Y39(6.495,11) Y41(8.227,11) Y43(9.959,11) Y45(11.691,11) Y47(13.423,11) Y49(15.155,11) Y51(16.887,11) Y53(18.619,11) Y55(20.351,11) Y57(22.083,11) Y59(23.815,11) Y61(25.547,11)
  round 0.56 smd: A2(-25.547,20.5) A60(24.681,20.5) B1(-26.413,20) B61(25.547,20) C62(26.413,19.5) DA62(26.413,-19.5) DB1(-26.413,-20) DB61(25.547,-20) DC2(-25.547,-20.5) DC60(24.681,-20.5)
  round 0.533 smd: A4(-23.815,20.5) A58(22.949,20.5) B3(-24.681,20) B59(23.815,20) C2(-25.547,19.5) C60(24.681,19.5) CW62(26.413,-18.5) CY1(-26.413,-19) CY61(25.547,-19) D1(-26.413,19) D61(25.547,19) DA2(-25.547,-19.5) DA60(24.681,-19.5) DB3(-24.681,-20) DB59(23.815,-20) DC4(-23.815,-20.5) DC58(22.949,-20.5) E62(26.413,18.5)
